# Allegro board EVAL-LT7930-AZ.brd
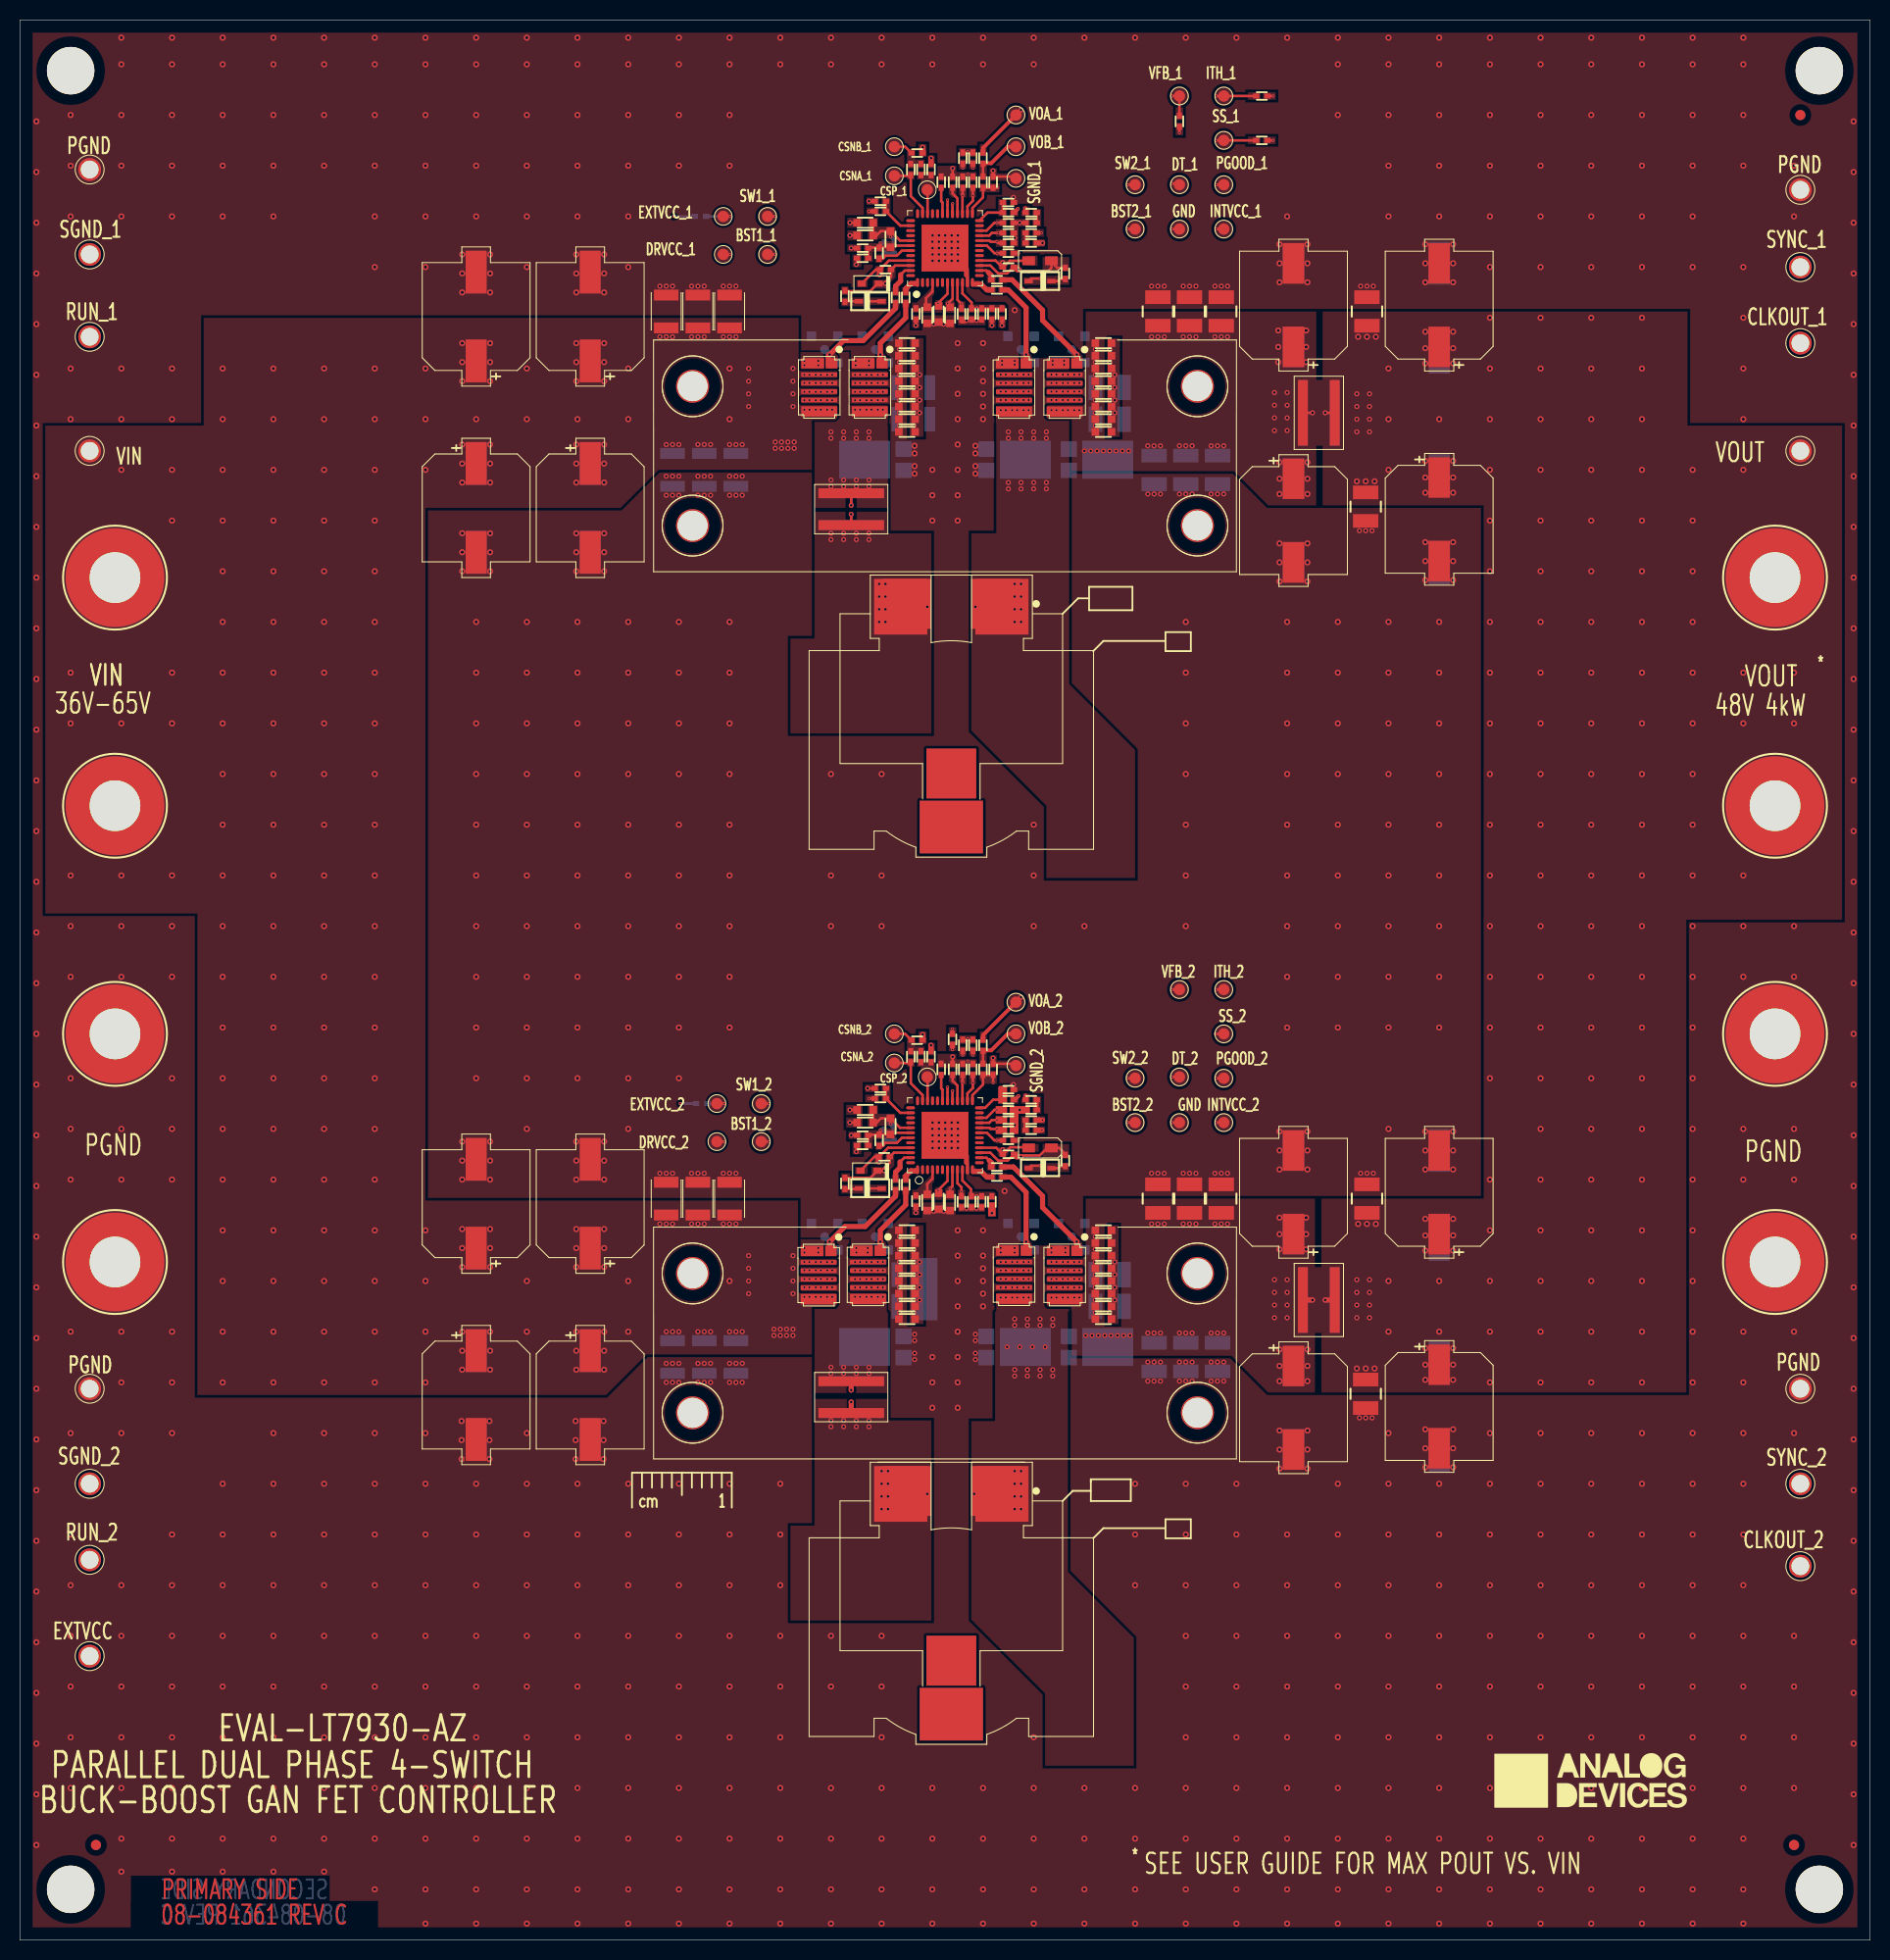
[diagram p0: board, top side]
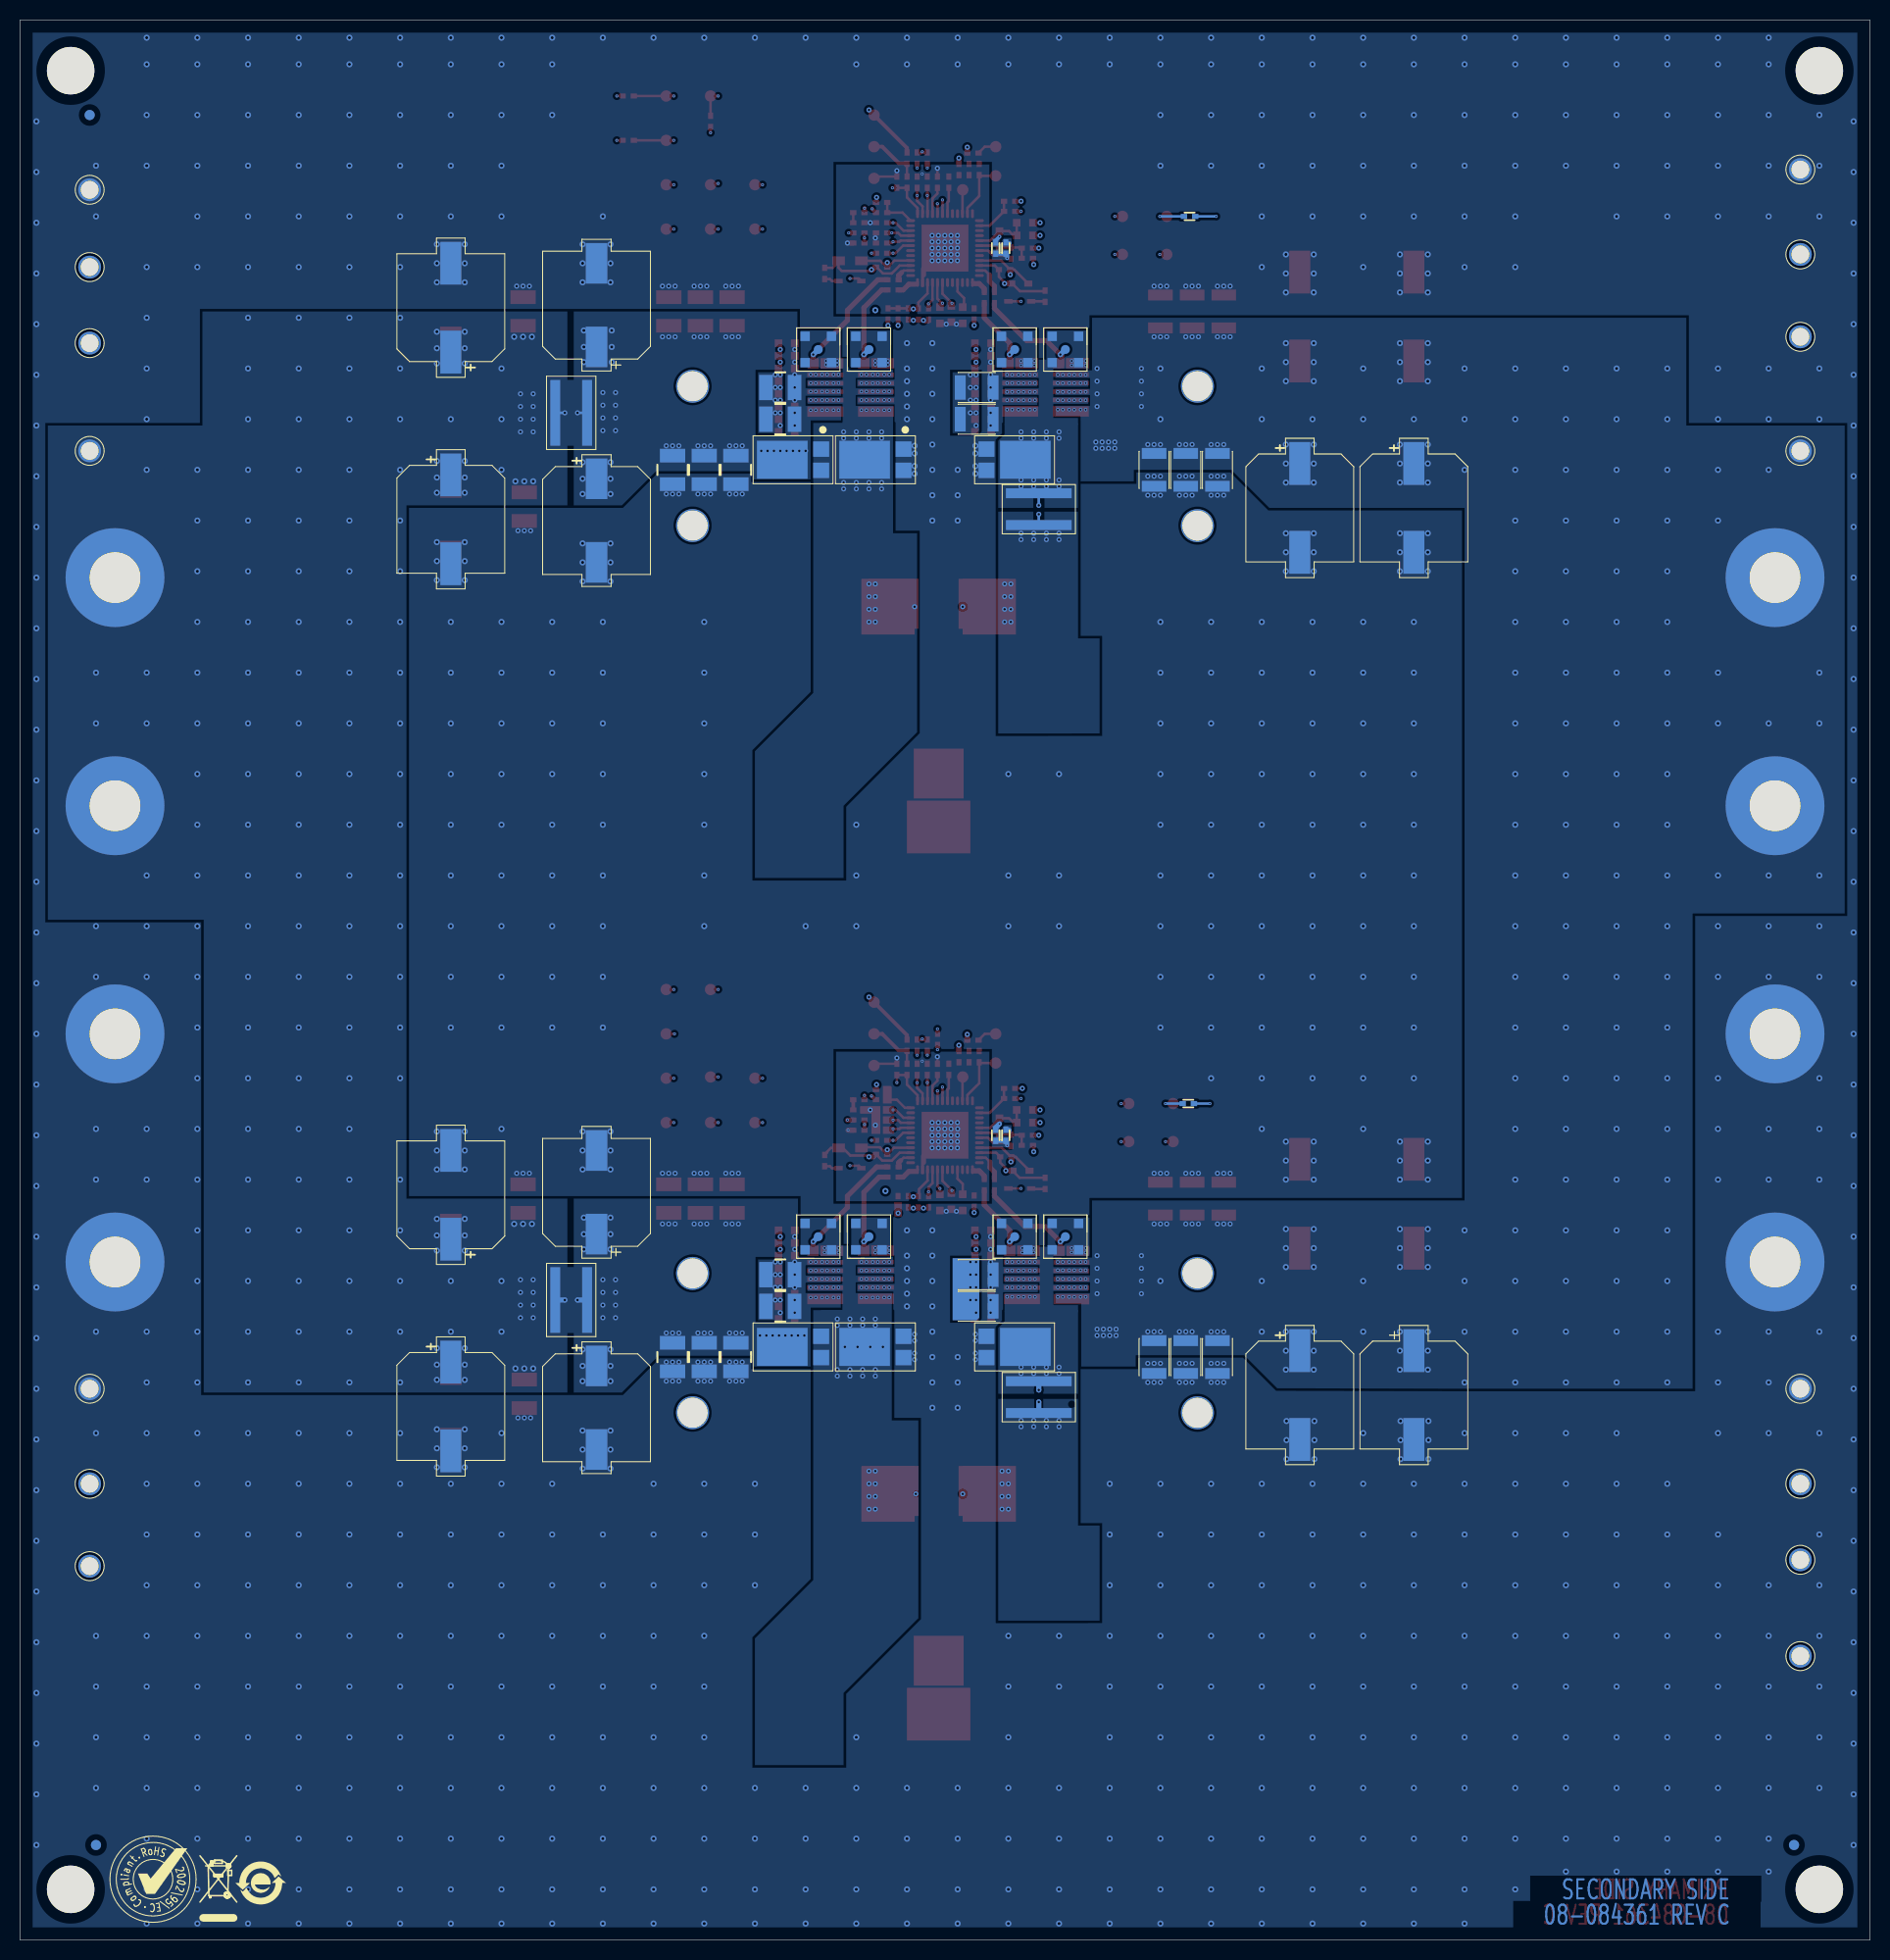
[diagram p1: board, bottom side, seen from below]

Outline 185.42 x 192.41 mm; copper layers: TOP, LAYER_2, LAYER_3, LAYER_4, LAYER_5, LAYER_6, LAYER_7, BOTTOM. Coordinates in mm from the lower left corner of the outline.
Outline path: 0,192.41 0,0 185.42,0 185.42,192.41 0,192.41

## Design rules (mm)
constraint set DEFAULT: min track width 0.254
net group _N77: nets _N77 UNNAMED_2_ADLTC7878V2_I124_BG2
net group SS_1: nets SS_1 SS_2
net group UNNAMED_1_ADLTC7878V2_I139_BG1: nets UNNAMED_1_ADLTC7878V2_I139_BG1 UNNAMED_1_RES_I73_N1
net group UNNAMED_1_ADLTC7878V2_I139_BG2: nets UNNAMED_1_ADLTC7878V2_I139_BG2 UNNAMED_1_RES_I87_N1
net group UNNAMED_1_ADLTC7878V2_I139_TG1: nets UNNAMED_1_ADLTC7878V2_I139_TG1 UNNAMED_1_RES_I72_N1
net group UNNAMED_1_ADLTC7878V2_I139_TG2: nets UNNAMED_1_ADLTC7878V2_I139_TG2 UNNAMED_1_RES_I115_N1
net group UNNAMED_2_ADLTC7878V2_I124_BG1: nets UNNAMED_2_ADLTC7878V2_I124_BG1 UNNAMED_2_RES_I64_N1
net group UNNAMED_2_ADLTC7878V2_I124_TG1: nets UNNAMED_2_ADLTC7878V2_I124_TG1 UNNAMED_2_RES_I63_N1
net group UNNAMED_2_ADLTC7878V2_I124_TG2: nets UNNAMED_2_ADLTC7878V2_I124_TG2 UNNAMED_2_RES_I106_N1
net group _N327: nets _N183 _N184 _N327 _N400 UNNAMED_1_ADLTC7878V2_I139_IS_1 UNNAMED_1_ADLTC7878V2_I139_IS_2 UNNAMED_1_ADLTC7878V2_I139_ISNS
net group _N339: nets _N144 _N145 _N339 _N399 UNNAMED_2_ADLTC7878V2_I124_IS_1 UNNAMED_2_ADLTC7878V2_I124_IS_2 UNNAMED_2_ADLTC7878V2_I124_ISNS
net group EXTVCC: nets EXTVCC EXTVCC_2 UNNAMED_1_ADLTC7878V2_I139_VOUT UNNAMED_2_ADLTC7878V2_I124_VOUT
net group ITH_1: nets ITH_1 ITH_2 UNNAMED_1_CAP_I38_N1 UNNAMED_2_CAP_I32_N1
net group UNNAMED_2_CAP_I92_N2: nets UNNAMED_2_ADLTC7878V2_I124_CSN UNNAMED_2_ADLTC7878V2_I124_CSP UNNAMED_2_CAP_I92_N2

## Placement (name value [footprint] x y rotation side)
C1  33uF  [CPLSMSQ406H413]  45.72 143.51 270 top
C2  33uF  [CPLSMSQ406H413]  57.15 143.51 270 top
C3  4.7uF  [C1210H87]  64.77 163.19 90 top
C4  4.7uF  [C1210H87]  67.94 163.19 90 top
C5  4.7uF  [C1210H87]  71.12 163.19 90 top
C6  4.7uF  [C1210H87]  71.75 147.32 270 bottom
C7  4.7uF  [C1210H87]  65.41 147.32 270 bottom
C8  4.7uF  [C1210H87]  68.58 147.32 270 bottom
C9  4.7uF  [C1210H87]  89.53 152.4 180 bottom
C10  4.7uF  [C1210H87]  89.53 155.57 180 bottom
C11  0.1UF  [C0402]  99.06 170.05 0 top
C12  1UF  [C0603]  90.93 162.81 270 top
C13  TBD0402  [C0402]  95.38 162.94 270 top
C14  100PF  [C0402]  99.06 172.09 0 top
C15  0.022uF  [C0402]  101.35 172.09 180 top
C16  0.47UF  [C0402]  86.74 167.39 180 top
C17  TBD0402  [C0402]  86.11 169.04 90 top
C18  0.01uF  [C0603]  87.25 170.43 90 top
C19  0.47UF  [C0402]  99.06 167.64 0 top
C20  1UF  [C0603]  93.22 162.81 270 top
C21  4.7uF  [C0402]  94.36 162.94 270 top
C22  TBD0402  [C0402]  90.3 177.42 90 top
C23  6.8uF  [C0603]  92.08 162.94 270 top
C24  10UF  [C1210H110]  120.4 163.19 90 top
C25  10UF  [C1210H110]  117.22 163.19 90 top
C26  10UF  [C1210H110]  114.05 163.19 90 top
C27  10UF  [C1210H110]  113.67 147.32 270 bottom
C28  10UF  [C1210H110]  120.02 147.32 270 bottom
C29  10UF  [C1210H110]  109.22 155.57 0 bottom
C30  10UF  [C1210H110]  109.22 152.4 0 bottom
C31  10UF  [C1210H110]  116.84 147.32 270 bottom
C32  47UF  [CPLSMSQ406H433]  142.24 163.83 90 top
C33  47UF  [CPLSMSQ406H433]  127.64 163.83 90 top
C34  33uF  [CPLSMSQ406H413]  45.72 54.61 270 bottom
C35  33uF  [CPLSMSQ406H413]  57.15 54.61 270 top
C36  4.7uF  [C1210H87]  64.77 74.3 90 top
C37  4.7uF  [C1210H87]  67.94 74.3 90 top
C38  4.7uF  [C1210H87]  71.12 74.3 90 top
C39  4.7uF  [C1210H87]  71.75 58.42 270 bottom
C40  4.7uF  [C1210H87]  68.58 58.42 270 bottom
C41  4.7uF  [C1210H87]  65.41 58.42 270 bottom
C42  4.7uF  [C1210H87]  89.53 66.67 180 bottom
C43  4.7uF  [C1210H87]  89.53 63.5 180 bottom
C44  0.1UF  [C0402]  99.06 81.15 0 top
C45  1UF  [C0603]  90.93 73.91 270 top
C46  TBD0402  [C0402]  95.38 73.98 270 top
C47  100PF  [C0402]  99.06 83.19 0 top
C48  0.022uF  [C0402]  101.35 83.19 180 top
C49  0.47UF  [C0402]  86.61 78.49 180 top
C50  TBD0402  [C0402]  86.11 80.14 90 top
C51  0.01uF  [C0603]  87.25 81.53 90 top
C52  0.47UF  [C0402]  99.06 78.74 0 top
C53  1UF  [C0603]  93.22 73.91 270 top
C54  4.7uF  [C0402]  94.36 73.98 270 top
C55  TBD0402  [C0402]  90.3 88.52 90 top
C56  6.8uF  [C0603]  92.08 74.04 270 top
C57  10UF  [C1210H110]  116.84 58.42 270 bottom
C58  10UF  [C1210H110]  113.67 58.42 270 bottom
C59  10UF  [C1210H110]  117.22 74.3 90 top
C60  10UF  [C1210H110]  120.02 58.42 270 bottom
C61  10UF  [C1210H110]  114.05 74.3 90 top
C62  10UF  [C1210H110]  120.4 74.3 90 top
C63  10UF  [C1210H110]  109.22 66.67 0 bottom
C64  10UF  [C1210H110]  109.22 63.5 0 bottom
C65  47UF  [CPLSMSQ406H433]  142.24 74.93 90 top
C66  47UF  [CPLSMSQ406H433]  127.64 74.93 90 top
C67  TBD0402  [C0402]  99.06 171.07 0 top
C68  TBD0402  [C0402]  99.06 82.17 0 top
C69  1UF  [C0603]  88.9 160.02 180 top
C70  1UF  [C0603]  88.9 158.75 180 top
C71  1UF  [C0603]  88.9 157.48 180 top
C72  1UF  [C0603]  88.9 156.21 180 top
C73  1UF  [C0603]  88.9 154.94 180 top
C74  1UF  [C0603]  88.9 153.67 180 top
C75  1UF  [C0603]  88.9 152.4 180 top
C76  1UF  [C0603]  88.9 151.13 180 top
C77  1UF  [C0603]  108.58 160.02 0 top
C78  1UF  [C0603]  108.58 158.75 0 top
C79  1UF  [C0603]  108.58 157.48 0 top
C80  1UF  [C0603]  108.58 156.21 0 top
C81  1UF  [C0603]  108.58 154.94 0 top
C82  1UF  [C0603]  108.58 153.67 0 top
C83  1UF  [C0603]  108.58 152.4 0 top
C84  1UF  [C0603]  108.58 151.13 0 top
C85  47UF  [CPLSMSQ406H433]  127.64 142.24 270 top
C86  47UF  [CPLSMSQ406H433]  127.64 142.24 270 bottom
C87  1UF  [C0603]  88.9 71.12 180 top
C88  1UF  [C0603]  88.9 69.85 180 top
C89  1UF  [C0603]  88.9 68.58 180 top
C90  1UF  [C0603]  88.9 67.31 180 top
C91  1UF  [C0603]  88.9 66.04 180 top
C92  1UF  [C0603]  88.9 64.77 180 top
C93  1UF  [C0603]  88.9 63.5 180 top
C94  1UF  [C0603]  88.9 62.23 180 top
C95  1UF  [C0603]  108.58 71.12 0 top
C96  1UF  [C0603]  108.58 69.85 0 top
C97  1UF  [C0603]  108.58 68.58 0 top
C98  1UF  [C0603]  108.58 67.31 0 top
C99  1UF  [C0603]  108.58 66.04 0 top
C100  1UF  [C0603]  108.58 64.77 0 top
C101  1UF  [C0603]  108.58 63.5 0 top
C102  1UF  [C0603]  108.58 62.23 0 top
C103  47UF  [CPLSMSQ406H433]  127.64 53.34 270 bottom
C104  47UF  [CPLSMSQ406H433]  127.64 53.34 270 top
C176  33uF  [CPLSMSQ406H413]  45.72 143.51 270 bottom
C177  33uF  [CPLSMSQ406H413]  57.15 143.51 270 bottom
C178  47UF  [CPLSMSQ406H433]  142.24 142.37 270 top
C179  47UF  [CPLSMSQ406H433]  127.64 163.83 90 bottom
C180  33uF  [CPLSMSQ406H413]  45.72 54.61 270 top
C181  33uF  [CPLSMSQ406H413]  57.15 54.61 270 bottom
C182  47UF  [CPLSMSQ406H433]  142.24 53.47 270 top
C183  47UF  [CPLSMSQ406H433]  127.64 74.93 90 bottom
C196  10UF  [C1210H110]  134.87 143.64 270 top
C197  10UF  [C1210H110]  135 163.19 90 top
C198  10UF  [C1210H110]  135 74.3 90 top
C199  10UF  [C1210H110]  134.87 54.74 270 top
C206  33uF  [CPLSMSQ406H413]  45.72 162.69 90 top
C207  33uF  [CPLSMSQ406H413]  57.15 162.69 90 top
C208  33uF  [CPLSMSQ406H413]  142.24 163.58 90 bottom
C209  33uF  [CPLSMSQ406H413]  142.24 142.37 270 bottom
C210  33uF  [CPLSMSQ406H413]  45.72 73.79 90 top
C211  33uF  [CPLSMSQ406H413]  57.15 73.79 90 top
C212  33uF  [CPLSMSQ406H413]  142.24 74.68 90 bottom
C213  33uF  [CPLSMSQ406H413]  142.24 53.47 270 bottom
D1  BAT46WJ,115  [SOD323F]  85.22 164.21 0 top
D2  BAT46WJ,115  [SOD323F]  102.23 166.24 180 top
D3  BAT46WJ,115  [SOD323F]  85.22 75.31 0 top
D4  BAT46WJ,115  [SOD323F]  102.23 77.34 180 top
D5  CMOZ5L1 TR PBFREE  [SOD523_B]  85.22 165.99 180 top
D7  PMEG100T030ELPEZ  [SOT1289B]  85.72 148.34 180 bottom
D8  CMDZ5231B TR PBFREE  [SOD323]  102.23 168.28 180 top
D10  PMEG100T030ELPEZ  [SOT1289B]  85.72 59.44 180 bottom
D11  CMDZ5231B TR PBFREE  [SOD323]  102.23 79.38 180 top
D12  CMOZ5L1 TR PBFREE  [SOD523_B]  85.09 77.09 180 top
D13  PMEG100T030ELPEZ  [SOT1289B]  99.69 148.34 0 bottom
D14  PMEG100T030ELPEZ  [SOT1289B]  107.95 148.34 0 bottom
D15  PMEG100T030ELPEZ  [SOT1289B]  99.69 59.44 0 bottom
D16  PMEG100T030ELPEZ  [SOT1289B]  107.95 59.44 0 bottom
J1  CKFH1032-10  [CNCFCKFH1032-10]  9.53 113.67 0 top
J2  CKFH1032-10  [CNCFCKFH1032-10]  9.53 90.81 0 top
J3  CKFH1032-10  [CNCFCKFH1032-10]  175.9 113.67 0 top
J4  CKFH1032-10  [CNCFCKFH1032-10]  175.9 90.81 0 top
J5  CKFH1032-10  [CNCFCKFH1032-10]  9.53 136.53 0 top
J6  CKFH1032-10  [CNCFCKFH1032-10]  9.53 67.94 0 top
J7  CKFH1032-10  [CNCFCKFH1032-10]  175.9 136.53 0 top
J8  CKFH1032-10  [CNCFCKFH1032-10]  175.9 67.94 0 top
J12  0734152063  [CNSMASQ136H203]  105.41 159.38 180 bottom
J13  0734152063  [CNSMASQ136H203]  80.64 70.48 180 bottom
J14  0734152063  [CNSMASQ136H203]  85.72 70.48 180 bottom
J15  0734152063  [CNSMASQ136H203]  100.33 70.48 180 bottom
J16  0734152063  [CNSMASQ136H203]  105.41 70.48 180 bottom
J17  0734152063  [CNSMASQ136H203]  100.33 159.38 180 bottom
J18  0734152063  [CNSMASQ136H203]  80.64 159.38 180 bottom
J19  0734152063  [CNSMASQ136H203]  85.72 159.38 180 bottom
L1  6.8UH  [LSML1102W764H728]  93.34 122.05 180 top
L1_1  2.2UH  [LSML858W571H571]  93.34 125.4 180 top
L2  6.8UH  [LSML1102W764H728]  93.34 33.15 180 top
L2_1  2.2UH  [LSML858W571H571]  93.34 36.5 180 top
NOREF  -  []  265.1 155.59 0 top
NOREF#2  -  [unnamed#2]  7.62 9.53 0 top
NOREF#3  -  [unnamed#2]  5.08 187.32 180 top
NOREF#4  -  []  -55.88 -186.06 0 top
NOREF#5  -  []  97.16 201.93 0 top
NOREF#6  -  []  0 192.41 0 top
NOREF#7  -  []  25.4 5.71 270 top
NOREF#8  -  []  185.42 0 90 top
NOREF#9  VAL  []  92.71 59.82 0 top
NOREF#10  -  []  -55.88 -186.06 0 top
NOREF#11  -  []  0 0 0 top
NOREF#12  -  []  185.42 0 90 top
NOREF#13  -  [unnamed#2]  177.8 9.53 0 top
NOREF#14  -  [unnamed#2]  178.44 182.88 0 top
NOREF#15  -  [unnamed#2]  180.34 187.32 180 top
NOREF#16  -  []  301.29 97.81 0 top
NOREF#17  -  []  0 192.41 270 top
NOREF#18  -  []  33.27 -151.76 0 top
NOREF#19  -  []  -201.93 -255.91 0 top
NOREF#20  VAL  []  92.71 148.72 0 top
NOREF#21  -  []  157.35 14.61 0 top
NOREF#22  -  [unnamed#2]  5.08 5.08 180 top
NOREF#23  -  []  326.06 48.28 0 top
NOREF#24  -  []  185.42 192.41 180 top
NOREF#25  -  []  -201.93 -255.91 0 top
NOREF#26  -  [unnamed#2]  180.34 5.08 180 top
NOREF#27  -  []  269.37 142.24 0 top
NOREF#28  -  []  256.97 -50.4 0 top
NOREF#29  -  []  61.34 43.33 0 top
NOREF#30  -  []  -55.88 -186.06 0 top
NOREF#31  -  []  165.74 1.91 180 bottom
NOREF#32  -  []  161.29 5.71 180 bottom
NOREF#33  -  [unnamed#2]  7.62 9.53 180 bottom
NOREF#34  -  [unnamed#2]  177.8 9.53 180 bottom
NOREF#35  -  []  172.09 6.1 180 bottom
NOREF#36  -  [unnamed#2]  178.44 182.88 180 bottom
P1  9774010243R  [CNWURTH9774010243R]  67.41 155.7 0 top
P2  9774010243R  [CNWURTH9774010243R]  67.41 141.73 0 top
P3  9774010243R  [CNWURTH9774010243R]  118.01 155.7 0 top
P4  9774010243R  [CNWURTH9774010243R]  118.01 141.74 0 top
P5  9774010243R  [CNWURTH9774010243R]  67.41 66.8 0 top
P6  9774010243R  [CNWURTH9774010243R]  67.41 52.83 0 top
P7  9774010243R  [CNWURTH9774010243R]  118.01 66.8 0 top
P8  9774010243R  [CNWURTH9774010243R]  118.01 52.84 0 top
Q1  EPC2361  [DIE7_5X3]  80.11 155.59 270 top
Q2  EPC2361  [DIE7_5X3]  85.18 155.59 270 top
Q3  EPC2361  [DIE7_5X3]  99.62 155.57 270 top
Q4  EPC2361  [DIE7_5X3]  104.7 155.57 270 top
Q5  EPC2361  [DIE7_5X3]  80.05 66.63 270 top
Q6  EPC2361  [DIE7_5X3]  85 66.66 270 top
Q7  EPC2361  [DIE7_5X3]  99.63 66.67 270 top
Q8  EPC2361  [DIE7_5X3]  104.71 66.65 270 top
R1  0  [R0402]  93.46 90.25 270 top
R2  0  [R0402]  98.42 162.94 270 top
R3  0  [R0402]  124.46 180.34 0 top
R4  0  [R0402]  124.46 184.78 0 top
R5  0  [R0402]  116.2 182.25 270 top
R6  1  [R0402]  89.79 74.04 90 top
R7  301K  [R0402]  97.41 162.94 90 top
R8  10.7K  [R0402]  96.39 162.94 90 top
R9  0  [R0402]  87.76 164.59 90 top
R10  0  [R0402]  88.77 164.59 90 top
R11  TBD0402  [R0402]  101.35 171.07 180 top
R12  9.09K  [R0402]  101.35 173.1 0 top
R13  0  [R0402]  84.45 168.53 0 top
R14  0.002  [R1225H28]  83.31 143.38 270 top
R15  0.002  [R1225H28]  83.31 143.38 270 bottom
R16  1  [R0603]  84.71 170.81 0 top
R17  0  [R0402]  86.61 169.54 90 bottom
R18  54.9K  [R0402]  93.47 176.15 90 top
R19  TBD0402  [R0402]  84.45 169.54 0 top
R20  TBD0402  [R0402]  92.33 176.15 90 top
R21  TBD0402  [R0402]  87.63 169.54 90 bottom
R22  0  [R0402]  95.5 176.15 90 top
R23  TBD0603  [R0603]  84.71 172.09 0 top
R24  0  [R0402]  94.49 176.15 90 top
R25  TBD0402  [R0402]  94.49 178.56 90 top
R26  TBD0402  [R0402]  95.5 178.56 90 top
R27  100K  [R0402]  99.06 169.04 0 top
R28  0  [R0402]  97.92 165.35 180 top
R29  0  [R0402]  89.28 177.42 90 top
R30  0  [R0402]  97.92 166.37 180 top
R31  0  [R0402]  91.31 177.42 90 top
R32  0  [R0402]  89.92 179.07 0 top
R33  0  [R1225H28]  130.18 153.03 0 top
R34  0  [R0402]  96.52 178.56 270 top
R35  475K  [R0402]  96.52 176.15 270 top
R36  10K  [R0402]  97.54 176.15 90 top
R37  301K  [R0402]  97.41 73.98 90 top
R38  10.7K  [R0402]  96.39 73.98 90 top
R39  0  [R0402]  87.76 75.69 90 top
R40  0  [R0402]  88.77 75.69 90 top
R41  TBD0402  [R0402]  101.35 82.17 180 top
R42  9.09K  [R0402]  101.35 84.2 0 top
R43  0  [R0402]  84.45 79.63 0 top
R44  0.002  [R1225H28]  83.31 54.41 270 top
R45  0.002  [R1225H28]  83.31 54.41 270 bottom
R46  1  [R0603]  84.71 81.92 0 top
R47  0  [R0402]  86.61 80.64 90 bottom
R48  54.9K  [R0402]  93.47 87.25 90 top
R49  TBD0402  [R0402]  84.45 80.64 0 top
R50  TBD0402  [R0402]  92.33 87.25 90 top
R51  TBD0402  [R0402]  87.63 80.64 90 bottom
R52  0  [R0402]  95.5 87.25 90 top
R53  TBD0603  [R0603]  84.71 83.19 0 top
R54  0  [R0402]  94.49 87.25 90 top
R55  TBD0402  [R0402]  94.49 89.66 90 top
R56  TBD0402  [R0402]  95.5 89.66 90 top
R57  100K  [R0402]  99.06 80.14 0 top
R58  0  [R0402]  97.92 76.45 180 top
R59  0  [R0402]  89.28 88.52 90 top
R60  0  [R0402]  97.92 77.47 180 top
R61  0  [R0402]  91.31 88.52 90 top
R62  0  [R0402]  89.92 90.17 0 top
R63  0  [R1225H28]  130.18 64.14 0 top
R64  0  [R0402]  96.52 89.66 270 top
R65  475K  [R0402]  96.52 87.25 270 top
R66  10K  [R0402]  97.54 87.25 90 top
R67  1  [R0402]  86.23 84.33 0 top
R68  5.1  [R0402]  86.23 85.34 180 top
R69  1  [R0402]  89.79 162.94 90 top
R70  1  [R0402]  86.23 173.23 0 top
R71  5.1  [R0402]  86.23 174.24 180 top
R72  21K  [R0402]  99.06 174.12 0 top
R73  27.4K  [R0402]  101.35 170.05 0 top
R74  953K  [R0402]  99.06 173.1 180 top
R75  21K  [R0402]  99.06 85.22 0 top
R76  27.4K  [R0402]  101.35 81.15 0 top
R77  953K  [R0402]  99.06 84.2 180 top
R78  1  [R0402]  82.68 164.72 90 top
R79  1  [R0402]  104.78 167 90 top
R80  1  [R0402]  82.68 75.82 90 top
R81  1  [R0402]  104.78 78.11 90 top
R82  0  [R0402]  68.2 172.72 180 bottom
R83  0  [R0402]  68.33 83.82 180 bottom
R190  0  [R1225H28]  130.18 153.03 0 bottom
R191  0  [R1225H28]  130.18 64.14 0 bottom
TP1  2308-2-00-80-00-00-07-0  [CNMILLMAX2308]  6.99 149.22 0 top
TP2  TESTPAD  [TPSMC40]  116.2 175.9 0 top
TP3  TESTPAD  [TPSMC40]  116.2 171.45 0 top
TP4  2308-2-00-80-00-00-07-0  [CNMILLMAX2308]  6.99 55.24 0 top
TP5  2308-2-00-80-00-00-07-0  [CNMILLMAX2308]  6.99 160.66 0 top
TP6  2308-2-00-80-00-00-07-0  [CNMILLMAX2308]  6.99 168.91 0 top
TP7  2308-2-00-80-00-00-07-0  [CNMILLMAX2308]  178.44 167.64 0 top
TP8  2308-2-00-80-00-00-07-0  [CNMILLMAX2308]  178.44 160.02 0 top
TP9  TESTPAD  [TPSMC40]  120.65 180.34 0 top
TP10  TESTPAD  [TPSMC40]  120.65 184.78 0 top
TP11  TESTPAD  [TPSMC40]  87.63 176.78 90 top
TP12  TESTPAD  [TPSMC40]  70.48 172.72 0 top
TP13  TESTPAD  [TPSMC40]  87.63 179.71 90 top
TP14  TESTPAD  [TPSMC40]  120.65 171.45 0 top
TP15  TESTPAD  [TPSMC40]  120.65 175.9 0 top
TP16  TESTPAD  [TPSMC40]  90.93 175.39 90 top
TP17  TESTPAD  [TPSMC40]  70.48 168.91 0 top
TP18  TESTPAD  [TPSMC40]  116.2 184.78 0 top
TP19  TESTPAD  [TPSMC40]  99.82 182.88 90 top
TP20  TESTPAD  [TPSMC40]  99.82 179.71 90 top
TP21  TESTPAD  [TPSMC40]  99.82 176.53 90 top
TP22  2308-2-00-80-00-00-07-0  [CNMILLMAX2308]  178.44 149.22 0 top
TP23  TESTPAD  [TPSMC40]  116.2 86.49 0 top
TP24  TESTPAD  [TPSMC40]  116.2 81.92 0 top
TP25  2308-2-00-80-00-00-07-0  [CNMILLMAX2308]  178.44 55.24 0 top
TP26  TESTPAD  [TPSMC40]  120.65 90.81 0 top
TP27  TESTPAD  [TPSMC40]  120.65 95.25 0 top
TP28  TESTPAD  [TPSMC40]  74.93 168.91 0 top
TP29  TESTPAD  [TPSMC40]  74.93 172.72 0 top
TP30  2308-2-00-80-00-00-07-0  [CNMILLMAX2308]  6.99 38.1 0 top
TP31  2308-2-00-80-00-00-07-0  [CNMILLMAX2308]  6.99 45.72 0 top
TP32  2308-2-00-80-00-00-07-0  [CNMILLMAX2308]  178.44 45.72 0 top
TP33  2308-2-00-80-00-00-07-0  [CNMILLMAX2308]  178.44 37.47 0 top
TP34  2308-2-00-80-00-00-07-0  [CNMILLMAX2308]  6.99 177.42 0 top
TP35  2308-2-00-80-00-00-07-0  [CNMILLMAX2308]  178.44 175.39 0 top
TP36  2308-2-00-80-00-00-07-0  [CNMILLMAX2308]  6.99 28.45 90 top
TP37  TESTPAD  [TPSMC40]  69.85 83.82 0 top
TP38  TESTPAD  [TPSMC40]  87.63 90.81 90 top
TP39  TESTPAD  [TPSMC40]  120.65 81.92 0 top
TP40  TESTPAD  [TPSMC40]  120.65 86.36 0 top
TP41  TESTPAD  [TPSMC40]  90.93 86.49 90 top
TP42  TESTPAD  [TPSMC40]  69.85 80.01 0 top
TP43  TESTPAD  [TPSMC40]  116.2 95.25 0 top
TP44  TESTPAD  [TPSMC40]  99.82 93.98 90 top
TP45  TESTPAD  [TPSMC40]  99.82 90.81 90 top
TP46  TESTPAD  [TPSMC40]  99.82 87.63 90 top
TP47  TESTPAD  [TPSMC40]  111.76 175.9 0 top
TP48  TESTPAD  [TPSMC40]  111.76 171.45 0 top
TP49  TESTPAD  [TPSMC40]  74.3 80.01 0 top
TP50  TESTPAD  [TPSMC40]  74.3 83.82 0 top
TP51  TESTPAD  [TPSMC40]  111.76 86.36 0 top
TP52  TESTPAD  [TPSMC40]  111.76 81.92 0 top
TP53  TESTPAD  [TPSMC40]  87.63 87.88 0 top
U1  LT7930AUK#PBF  [QFN48_7X7_PAD4_7X4_7_A]  92.71 169.54 0 top
U2  LT7930AUK#PBF  [QFN48_7X7_PAD4_7X4_7_A]  92.71 80.64 0 top

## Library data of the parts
C1 C2 C34 C35 C176 C177 C180 C181 C206-C213 = CAPP: User Part Number: UPN; Tolerance: 20; alternate symbols: (CPLSMSQ406H413); tolerance: 20
C3-C10 C36-C43 = CAP: Tolerance: 10; User Part Number: UPN; alternate symbols: (C1210H87); tolerance: 10
C11 C15 C16 C19 C21 C44 C48 C49 C52 C54 = CAP: Tolerance: 10; User Part Number: UPN; alternate symbols: (C0402); tolerance: 10
C12 C18 C20 C23 C45 C51 C53 C56 C69-C84 C87-C102 = CAP: Tolerance: 10; User Part Number: UPN; alternate symbols: (C0603); tolerance: 10
C13 C17 C22 C46 C50 C55 C67 C68 = CAP: User Part Number: UPN; alternate symbols: (C0402)
C14 C47 = CAP: Tolerance: 20; User Part Number: UPN; alternate symbols: (C0402); tolerance: 20
C24-C31 C57-C64 C196-C199 = CAP: User Part Number: UPN; Tolerance: 10; alternate symbols: (C1210H110); tolerance: 10
C32 C33 C65 C66 C85 C86 C103 C104 C178 C179 C182 C183 = CAPP: User Part Number: UPN; Tolerance: 20; alternate symbols: (CPLSMSQ406H433); tolerance: 20
D1-D4 = DIOSCHOTTKY: Tolerance: N/A; User Part Number: UPN; alternate symbols: (SOD323F); tolerance: N/A
D5 D12 = DIOZNR: Tolerance: 5; User Part Number: UPN; alternate symbols: (SOD523_B); tolerance: 5
D7 D10 D13-D16 = DIOSCHOTTKY_3P: User Part Number: UPN; Tolerance: N/A; alternate symbols: (SOT1289B); tolerance: N/A
D8 D11 = DIOZNR: Tolerance: 5; User Part Number: UPN; alternate symbols: (SOD323); tolerance: 5
J1-J8 = CNTP1P: Tolerance: N/A; User Part Number: UPN; alternate symbols: (CNCFCKFH1032-10_C380D200); tolerance: N/A
J12-J19 = CNBNC5P: Tolerance: N/A; User Part Number: UPN; alternate symbols: (CNSMASQ136H203); tolerance: N/A
L1 L2 = IND: User Part Number: UPN; Tolerance: 15; alternate symbols: (LSML1102W764H728); tolerance: 15
L1_1 L2_1 = IND: Tolerance: 15; User Part Number: UPN; alternate symbols: (LSML858W571H571); tolerance: 15
NOREF#9 = -: Tolerance: TOL; User Part Number: UPN
NOREF#20 = -: User Part Number: UPN; Tolerance: TOL
P1-P8 = CN1P: Tolerance: N/A; User Part Number: UPN; alternate symbols: (CNWURTH9774010243R); tolerance: N/A
Q1-Q8 = TRANNGANFET7P_V3: User Part Number: UPN; Tolerance: N/A; alternate symbols: (DIE7_5X3); tolerance: N/A
R1-R5 R9 R10 R13 R17 R22 R24 R28-R32 R34 R39 R40 R43 R47 R52 R54 R58-R62 R64 R82 R83 = RES: Tolerance: JUMPER; User Part Number: UPN; alternate symbols: (R0402); tolerance: JUMPER
R6 R67-R71 = RES: Tolerance: 5; User Part Number: UPN; alternate symbols: (R0402); tolerance: 5
R7 R8 R12 R18 R27 R35-R38 R42 R48 R57 R65 R66 R72-R77 = RES: Tolerance: 1; User Part Number: UPN; alternate symbols: (R0402); tolerance: 1
R11 R19-R21 R25 R26 R41 R49-R51 R55 R56 R78-R81 = RES: User Part Number: UPN; alternate symbols: (R0402)
R14 R15 R44 R45 = RES: User Part Number: UPN; Tolerance: 2; alternate symbols: (R1225H28); tolerance: 2
R16 R23 R46 R53 = RES: User Part Number: UPN; alternate symbols: (R0603)
R33 R63 R190 R191 = RES: User Part Number: UPN; Tolerance: N/A; alternate symbols: (R1225H28); tolerance: N/A
TP1 TP4-TP8 TP22 TP25 TP30-TP36 = CNTP1P: User Part Number: UPN; Tolerance: N/A; alternate symbols: (CNMILLMAX2308); tolerance: N/A
TP2 TP3 TP9-TP21 TP23 TP24 TP26-TP29 TP37-TP53 = NCTESTPAD: Tolerance: N/A; User Part Number: UPN; alternate symbols: (TPSMC40); tolerance: N/A
U1 U2 = ADLT7930: Tolerance: N/A; User Part Number: UPN; alternate symbols: (QFN48_7X7_PAD4_7X4_7_A); tolerance: N/A

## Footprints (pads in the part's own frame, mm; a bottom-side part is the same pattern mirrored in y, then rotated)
C0402
  rect 0.635x0.508 smd: 1(-0.564,0) 2(0.564,0)
C0603
  rect 0.762x0.762 smd: 1(-0.813,0) 2(0.813,0)
C1210H87
  rect 1.092x2.464 smd: 1(-1.646,0) 2(1.646,0)
C1210H110
  rect 1.372x2.54 smd: 1(-1.431,0) 2(1.431,0)
CNCFCKFH1032-10
  round 9.906 hole 5.08: 1(0,0)
CNMILLMAX2308
  round 2.286 hole 1.778: 1(0,0)
CNSMASQ136H203
  round 0.889 smd: 1(0,0)
  rect 0.94x0.94 smd: 2(-1.32,-1.32) 3(1.32,-1.32) 4(1.32,1.32) 5(-1.32,1.32)
CNWURTH9774010243R
  round 3.302 hole 2.997 unplated: (0,0)
  round 0 smd: 1(0,0)
CPLSMSQ406H413
  rect 4.293x2.108 smd: N(4.45,0) P(-4.45,0)
CPLSMSQ406H433
  rect 4.064x2.159 smd: N(4.187,0) P(-4.187,0)
DIE7_5X3
  rect 1.041x1.143 smd: 1(-2.414,1.222)
  rect 1.041x2.286 smd: 2(-2.414,-0.658)
  rect 0.457x3.607 smd: 3(-1.275,0) 4(-0.425,0) 5(0.425,0) 6(1.275,0)
  rect 1.041x3.607 smd: 7(2.414,0)
LSML858W571H571
  rect 5.004x5.004 smd: (0,8.502) 1(-4.502,-8.502) 2(4.502,-8.502)
LSML1102W764H728
  rect 6.35x5.283 smd: (0,10.514)
  rect 5.334x5.588 smd: 1(-5.075,-11.56) 2(5.075,-11.56)
QFN48_7X7_PAD4_7X4_7_A
  oval 0.305x0.889 smd: 1(-2.75,-3.45) 2(-2.25,-3.45) 3(-1.75,-3.45) 4(-1.25,-3.45) 5(-0.75,-3.45) 6(-0.25,-3.45) 7(0.25,-3.45) 8(0.75,-3.45) 9(1.25,-3.45) 10(1.75,-3.45) 11(2.25,-3.45) 12(2.75,-3.45) 25(2.75,3.45) 26(2.25,3.45) 27(1.75,3.45) 28(1.25,3.45) 29(0.75,3.45) 30(0.25,3.45) 31(-0.25,3.45) 32(-0.75,3.45) 33(-1.25,3.45) 34(-1.75,3.45) 35(-2.25,3.45) 36(-2.75,3.45)
  oval 0.889x0.305 smd: 13(3.45,-2.75) 14(3.45,-2.25) 15(3.45,-1.75) 16(3.45,-1.25) 17(3.45,-0.75) 18(3.45,-0.25) 19(3.45,0.25) 20(3.45,0.75) 21(3.45,1.25) 22(3.45,1.75) 23(3.45,2.25) 24(3.45,2.75) 37(-3.45,2.75) 38(-3.45,2.25) 39(-3.45,1.75) 40(-3.45,1.25) 41(-3.45,0.75) 42(-3.45,0.25) 43(-3.45,-0.25) 44(-3.45,-0.75) 45(-3.45,-1.25) 46(-3.45,-1.75) 47(-3.45,-2.25) 48(-3.45,-2.75)
  rect 4.699x4.699 smd: 49(0,0)
R0402
  rect 0.635x0.508 smd: 1(-0.564,0) 2(0.564,0)
R0603
  rect 0.762x0.762 smd: 1(-0.813,0) 2(0.813,0)
R1225H28
  rect 0.991x6.579 smd: 1(-1.595,0) 2(1.595,0)
SOD323
  rect 1.27x0.889 smd: A(1.143,0) C(-1.143,0)
SOD323F
  rect 0.838x0.457 smd: A(1.14,0) C(-1.14,0)
SOD523_B
  rect 0.813x0.61 smd: A(0.85,0) C(-0.85,0)
SOT1289B
  rect 1.6x1.549 smd: 1(-2.83,-1.065) 2(-2.83,1.065)
  rect 5.08x3.81 smd: 3(1.07,0)
TPSMC40
  round 1.143 smd: 1(0,0)
unnamed#2
  round 1.016 smd: (0,0)

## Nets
SGND: C11.2(N2) C13.2(N2) C14.2(N2) C15.2(N2) C21.2(N2) C44.2(N2) C46.2(N2) C47.2(N2) C48.2(N2) C54.2(N2) C67.2(N2) C68.2(N2) R8.1 R18.2(N2) R20.2(N2) R22.2(N2) R24.2(N2) R36.2(N2) R38.1 R48.2(N2) R50.2(N2) R52.2(N2) R54.2(N2) R66.2(N2) R73.2(N2) R76.2(N2) TP3.1(N1) TP6.1(N1) TP21.1(N1) TP24.1(N1) TP31.1(N1) TP46.1(N1) U1.49 U2.49
VIN: C1.P C2.P C3.1 C4.1 C5.1 C6.1 C7.1 C8.1 C9.1 C10.1 C34.P C35.P C36.1 C37.1 C38.1 C39.1 C40.1 C41.1 C42.1 C43.1 C69.1 C70.1 C71.1 C72.1 C73.1 C74.1 C75.1 C76.1 C87.1 C88.1 C89.1 C90.1 C91.1 C92.1 C93.1 C94.1 C176.P C177.P C180.P C181.P C206.P C207.P C210.P C211.P J1.1(N1) J5.1(N1) Q1.3 Q1.5 Q1.7 Q5.3 Q5.5 Q5.7 R6.1 R7.1 R37.1 R69.1 R74.1 R77.1 TP1.1(N1)
_N4: C67.1 R11.2(N2) R73.1 U1.21
_N10: R11.1 TP2.1(N1)
_N12: R72.1 R74.2(N2) U1.24
_N77: J15.1 Q7.1 R58.1
_N135: R41.1 TP23.1(N1)
_N140: R75.1 R77.2(N2) U2.24
_N144: D3.C R80.1
_N145: D4.C R81.1
_N183: D2.C R79.1
_N184: D1.C R78.1
_N327: L1.2(N2) L1_1.2(N2) R14.2(N2) R15.2(N2) R16.1 R19.1
_N339: L2.2(N2) L2_1.2(N2) R44.2(N2) R45.2(N2) R46.1 R49.1
_N377: C52.1 D11.A(P) D15.3(C) D16.1 D16.2 J16.2 J16.3 J16.4 J16.5(SH4) L2.1 L2_1.1 Q7.3 Q7.5 Q7.7 Q8.2 Q8.4 Q8.6(S3) R53.1 TP51.1(N1) U2.16
_N381: C19.1 D8.A(P) D13.3(C) D14.1 D14.2 J12.2 J12.3 J12.4 J12.5(SH4) L1.1 L1_1.1 Q3.3 Q3.5 Q3.7 Q4.2 Q4.4 Q4.6(S3) R23.1 TP47.1(N1) U1.16
_N399: C49.2(N2) D10.3(C) D12.A(P) J13.2 J13.3 J13.4 J13.5(SH4) Q5.2 Q5.4 Q5.6(S3) Q6.3 Q6.5 Q6.7 R43.1 R44.1 R45.1 TP50.1(N1) U2.45
_N400: C16.2(N2) D5.A(P) D7.3(C) J18.2 J18.3 J18.4 J18.5(SH4) Q1.2 Q1.4 Q1.6(S3) Q2.3 Q2.5 Q2.7 R13.1 R14.1 R15.1 TP29.1(N1) U1.45
CLKOUT_1: R1.1 TP8.1(N1) U1.29
CLKOUT_2: TP33.1(N1) U2.29
DRVCC_1: C23.1 D1.A(P) D2.A(P) TP17.1(N1) U1.7
DRVCC_2: C56.1 D3.A(P) D4.A(P) TP42.1(N1) U2.7
EXTVCC: R82.2(N2) R83.2(N2) TP36.1(N1)
EXTVCC_1: C20.1 R70.1 R82.1 TP12.1(N1) U1.8
EXTVCC_2: C53.1 R67.1 R83.1 TP37.1(N1) U2.8
GROUND: C1.N(N2) C2.N(N2) C3.2(N2) C4.2(N2) C5.2(N2) C6.2(N2) C7.2(N2) C8.2(N2) C9.2(N2) C10.2(N2) C12.2(N2) C20.2(N2) C23.2(N2) C24.2(N2) C25.2(N2) C26.2(N2) C27.2(N2) C28.2(N2) C29.2(N2) C30.2(N2) C31.2(N2) C32.N(N2) C33.N(N2) C34.N(N2) C35.N(N2) C36.2(N2) C37.2(N2) C38.2(N2) C39.2(N2) C40.2(N2) C41.2(N2) C42.2(N2) C43.2(N2) C45.2(N2) C53.2(N2) C56.2(N2) C57.2(N2) C58.2(N2) C59.2(N2) C60.2(N2) C61.2(N2) C62.2(N2) C63.2(N2) C64.2(N2) C65.N(N2) C66.N(N2) C69.2(N2) C70.2(N2) C71.2(N2) C72.2(N2) C73.2(N2) C74.2(N2) C75.2(N2) C76.2(N2) C77.2(N2) C78.2(N2) C79.2(N2) C80.2(N2) C81.2(N2) C82.2(N2) C83.2(N2) C84.2(N2) C85.N(N2) C86.N(N2) C87.2(N2) C88.2(N2) C89.2(N2) C90.2(N2) C91.2(N2) C92.2(N2) C93.2(N2) C94.2(N2) C95.2(N2) C96.2(N2) C97.2(N2) C98.2(N2) C99.2(N2) C100.2(N2) C101.2(N2) C102.2(N2) C103.N(N2) C104.N(N2) C176.N(N2) C177.N(N2) C178.N(N2) C179.N(N2) C180.N(N2) C181.N(N2) C182.N(N2) C183.N(N2) C196.2(N2) C197.2(N2) C198.2(N2) C199.2(N2) C206.N(N2) C207.N(N2) C208.N(N2) C209.N(N2) C210.N(N2) C211.N(N2) C212.N(N2) C213.N(N2) D7.1 D7.2 D10.1 D10.2 D13.1 D13.2 D15.1 D15.2 J2.1(N1) J4.1(N1) J6.1(N1) J8.1(N1) J14.2 J14.3 J14.4 J14.5(SH4) J15.2 J15.3 J15.4 J15.5(SH4) J17.2 J17.3 J17.4 J17.5(SH4) J19.2 J19.3 J19.4 J19.5(SH4) Q2.2 Q2.4 Q2.6(S3) Q3.2 Q3.4 Q3.6(S3) Q6.2 Q6.4 Q6.6(S3) Q7.2 Q7.4 Q7.6(S3) R72.2(N2) R75.2(N2) TP4.1(N1) TP25.1(N1) TP34.1(N1) TP35.1(N1) U1.11 U2.11
INTVCC_1: C21.1 R25.2(N2) R26.2(N2) R27.2(N2) TP14.1(N1) U1.9
INTVCC_2: C54.1 R55.2(N2) R56.2(N2) R57.2(N2) TP39.1(N1) U2.9
ITH_1: C14.1 R4.1 R12.1 TP10.1(N1) U1.22
ITH_2: C47.1 R4.2(N2) R42.1 TP27.1(N1) U2.22
RUN_1: C13.1 R2.1 R7.2(N2) R8.2(N2) TP5.1(N1) U1.10
RUN_2: C46.1 R2.2(N2) R37.2(N2) R38.2(N2) TP30.1(N1) U2.10
SS_1: C11.1 R3.1 TP9.1(N1) U1.20
SS_2: C44.1 R3.2(N2) TP26.1(N1) U2.20
SYNC_1: TP7.1(N1) U1.30
SYNC_2: R1.2(N2) TP32.1(N1) U2.30
UNNAMED_1_ADLTC7878V2_I139_BG1: R10.2(N2) U1.1
UNNAMED_1_ADLTC7878V2_I139_BG2: R28.2(N2) U1.12
UNNAMED_1_ADLTC7878V2_I139_BO_1: C19.2(N2) D8.C R79.2(N2) TP48.1(N1) U1.15
UNNAMED_1_ADLTC7878V2_I139_BOOS: C16.1 D5.C R78.2(N2) TP28.1(N1) U1.46
UNNAMED_1_ADLTC7878V2_I139_CSN: R29.1 TP11.1(N1) U1.35
UNNAMED_1_ADLTC7878V2_I139_CSP: C22.1 R31.1 TP16.1(N1) U1.34
UNNAMED_1_ADLTC7878V2_I139_FREQ: R18.1 U1.28
UNNAMED_1_ADLTC7878V2_I139_IS_1: C17.1 R17.1 R21.1 U1.43
UNNAMED_1_ADLTC7878V2_I139_IS_2: C17.2(N2) C18.1 R13.2(N2) R17.2(N2) R19.2(N2) U1.42
UNNAMED_1_ADLTC7878V2_I139_ISNS: C18.2(N2) R16.2(N2) R21.2(N2) R23.2(N2) U1.41
UNNAMED_1_ADLTC7878V2_I139_MODE: R22.1 R26.1 U1.26
UNNAMED_1_ADLTC7878V2_I139_PGOO: R27.1 TP15.1(N1) U1.19
UNNAMED_1_ADLTC7878V2_I139_PHAS: R24.1 R25.1 U1.27
UNNAMED_1_ADLTC7878V2_I139_SETC: R20.1 U1.31
UNNAMED_1_ADLTC7878V2_I139_TG1: R9.2(N2) U1.47
UNNAMED_1_ADLTC7878V2_I139_TG2: R30.2(N2) U1.14
UNNAMED_1_ADLTC7878V2_I139_VIN: C12.1 R69.2(N2) U1.4
UNNAMED_1_ADLTC7878V2_I139_VOUT: R70.2(N2) R71.1 U1.38(VOUT)
UNNAMED_1_CAP_I38_N1: C15.1 R12.2(N2)
UNNAMED_1_CAP_I100_N2: C22.2(N2) R29.2(N2) R32.1 TP13.1(N1)
UNNAMED_1_NCTESTPAD_I113_N1: R34.2(N2) R35.1 TP20.1(N1)
UNNAMED_1_RES_I72_N1: J18.1 Q1.1 R9.1
UNNAMED_1_RES_I73_N1: J19.1 Q2.1 R10.1
UNNAMED_1_RES_I87_N1: J17.1 Q3.1 R28.1
UNNAMED_1_RES_I115_N1: J12.1 Q4.1 R30.1
UNNAMED_2_ADLTC7878V2_I124_BG1: R40.2(N2) U2.1
UNNAMED_2_ADLTC7878V2_I124_BG2: R58.2(N2) U2.12
UNNAMED_2_ADLTC7878V2_I124_BO_1: C49.1 D12.C R80.2(N2) TP49.1(N1) U2.46
UNNAMED_2_ADLTC7878V2_I124_BOOS: C52.2(N2) D11.C R81.2(N2) TP52.1(N1) U2.15
UNNAMED_2_ADLTC7878V2_I124_CSN: R59.1 TP53.1(N1) U2.35
UNNAMED_2_ADLTC7878V2_I124_CSP: C55.1 R61.1 TP41.1(N1) U2.34
UNNAMED_2_ADLTC7878V2_I124_FREQ: R48.1 U2.28
UNNAMED_2_ADLTC7878V2_I124_IS_1: C50.2(N2) C51.1 R43.2(N2) R47.2(N2) R49.2(N2) U2.42
UNNAMED_2_ADLTC7878V2_I124_IS_2: C51.2(N2) R46.2(N2) R51.2(N2) R53.2(N2) U2.41
UNNAMED_2_ADLTC7878V2_I124_ISNS: C50.1 R47.1 R51.1 U2.43
UNNAMED_2_ADLTC7878V2_I124_ITHB: C68.1 R41.2(N2) R76.1 U2.21
UNNAMED_2_ADLTC7878V2_I124_MODE: R52.1 R56.1 U2.26
UNNAMED_2_ADLTC7878V2_I124_PGOO: R57.1 TP40.1(N1) U2.19
UNNAMED_2_ADLTC7878V2_I124_PHAS: R54.1 R55.1 U2.27
UNNAMED_2_ADLTC7878V2_I124_SETC: R50.1 U2.31
UNNAMED_2_ADLTC7878V2_I124_TG1: R39.2(N2) U2.47
UNNAMED_2_ADLTC7878V2_I124_TG2: R60.2(N2) U2.14
UNNAMED_2_ADLTC7878V2_I124_VIN: C45.1 R6.2(N2) U2.4
UNNAMED_2_ADLTC7878V2_I124_VOUT: R67.2(N2) R68.1 U2.38(VOUT)
UNNAMED_2_CAP_I32_N1: C48.1 R42.2(N2)
UNNAMED_2_CAP_I92_N2: C55.2(N2) R59.2(N2) R62.1 TP38.1(N1)
UNNAMED_2_NCTESTPAD_I104_N1: R64.2(N2) R65.1 TP45.1(N1)
UNNAMED_2_RES_I63_N1: J13.1 Q5.1 R39.1
UNNAMED_2_RES_I64_N1: J14.1 Q6.1 R40.1
UNNAMED_2_RES_I106_N1: J16.1 Q8.1 R60.1
VFB_1: R5.1 R35.2(N2) R36.1 TP18.1(N1) U1.25
VFB_2: R5.2(N2) R65.2(N2) R66.1 TP43.1(N1) U2.25
VOUT: C24.1 C25.1 C26.1 C27.1 C28.1 C29.1 C30.1 C31.1 C32.P C33.P C57.1 C58.1 C59.1 C60.1 C61.1 C62.1 C63.1 C64.1 C65.P C66.P C77.1 C78.1 C79.1 C80.1 C81.1 C82.1 C83.1 C84.1 C85.P C86.P C95.1 C96.1 C97.1 C98.1 C99.1 C100.1 C101.1 C102.1 C103.P C104.P C178.P C179.P C182.P C183.P C196.1 C197.1 C198.1 C199.1 C208.P C209.P C212.P C213.P D14.3(C) D16.3(C) J3.1(N1) J7.1(N1) Q4.3 Q4.5 Q4.7 Q8.3 Q8.5 Q8.7 R31.2(N2) R32.2(N2) R33.1 R33.2(N2) R34.1 R61.2(N2) R62.2(N2) R63.1 R63.2(N2) R64.1 R68.2(N2) R71.2(N2) R190.1 R190.2(N2) R191.1 R191.2(N2) TP19.1(N1) TP22.1(N1) TP44.1(N1)

Pads without a net: P1 1; P2 1; P3 1; P4 1; P5 1; P6 1; P7 1; P8 1; U1 2 3 5 6 13 17 18 23 32 33 36 37 39 40 44 48; U2 2 3 5 6 13 17 18 23 32 33 36 37 39 40 44 48

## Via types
v1: diameter 0.508, hole 0.254, TOP to BOTTOM, 571 vias
v2: diameter 0.356, hole 0.203, TOP to BOTTOM, 272 vias
v3: diameter 0.305, hole 0.152, TOP to BOTTOM, 88 vias
v4: diameter 0.61, hole 0.305, TOP to BOTTOM, 1157 vias

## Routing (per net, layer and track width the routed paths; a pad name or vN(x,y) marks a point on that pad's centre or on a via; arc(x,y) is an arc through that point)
SGND: length 218.4
  TOP w0.254: v1(93.47,88.51) R48.2 ; TP24.1 v3(115.44,81.92) ; TP46.1 99.64,87.81 R66.2 v1(97.54,88.39) ; TP21.1 99.64,176.71 R36.2 v1(97.54,177.29) ; C14.2 v1(100.2,172.09) C15.2 ; R18.2 v1(93.47,177.55) ; TP3.1 v3(115.44,171.45) ; v1(94.87,162.31) 94.69,162.12 94.36,162.12 C21.2 ; C11.2 99.62,170.49 v1(99.69,170.56) ; C13.2 R8.1
  TOP w0.381: C44.2 99.69,81.22 v1(99.69,81.66) 99.69,82.1 C68.2 ; C47.2 v1(100.2,83.19) C48.2
  TOP w0.508: R73.2 v1(102.49,170.05) ; R76.2 v3(102.43,81.15)
  LAYER_4 w1.27: TP31.1 12.83,45.72 41.78,74.68 59.37,74.68 71.69,87 86.23,87 91.31,81.92 v1(91.47,81.92) ; v1(91.47,170.81) 91.12,170.81 86.17,175.77 34.48,175.77 27.62,168.91 TP6.1
  LAYER_5 w0.381: v3(115.44,171.45) 113.79,169.8 111.38,169.8 ; 111.25,80.52 114.05,80.52 v3(115.44,81.92)
  vias: v1(91.44,170.18) v1(91.44,81.28) v1(91.47,169.54) v1(91.47,168.91) v1(91.47,168.28) v1(91.47,80.64) v1(91.47,80.01) v1(91.47,79.38) v1(92.1,170.81) v1(92.1,170.18) v1(92.1,169.54) v1(92.1,168.91) v1(92.1,168.28) v1(92.1,81.92) v1(92.1,81.28) v1(92.1,80.64) v1(92.1,80.01) v1(92.1,79.38) v1(92.74,170.81) v1(92.74,170.18) v1(92.74,169.54) v1(92.74,168.91) v1(92.74,168.28) v1(92.74,81.92) v1(92.74,81.28) v1(92.74,80.64) v1(92.74,80.01) v1(92.74,79.38) v1(93.37,170.81) v1(93.37,170.18) v1(93.37,169.54) v1(93.37,168.91) v1(93.37,168.28) v1(93.37,81.92) v1(93.37,81.28) v1(93.37,80.64) v1(93.37,80.01) v1(93.37,79.38) v1(94.01,170.81) v1(94.01,170.18) v1(94.01,169.54) v1(94.01,168.91) v1(94.01,168.28) v1(94.01,81.92) v1(94.01,81.28) v1(94.01,80.64) v1(94.01,80.01) v1(94.01,79.38) v1(94.87,73.34) v1(95.89,162.31) v1(95.89,73.34) v3(95,176.97) v3(95,88.07)
VIN: length 66.8
  TOP w0.254: R6.1 v1(89.79,72.9) ; R7.1 v1(97.41,161.8) 97.44,161.77 ; R69.1 v1(89.79,161.8)
  TOP w0.381: R74.1 99.63,173.1 v3(100.01,173.48) ; v3(100.08,84.58) 99.69,84.2 R77.1
  TOP w0.508: R37.1 v1(97.41,72.83)
  LAYER_3 w0.254: v1(97.41,161.8) 96.52,160.91 91.31,160.91 90.42,161.8 v1(89.79,161.8) 89.6,161.61 v1(89.6,159.38) ; v1(89.6,70.48) 89.6,72.71 v1(89.79,72.9) 90.17,72.9 91.19,71.88 96.46,71.88 v1(97.41,72.83)
  LAYER_5 w0.254: v1(97.41,72.83) 99.38,72.83 103.89,77.34 103.89,84.33 102.62,85.6 100.71,85.6 100.08,84.96 v3(100.08,84.58) ; v3(100.01,173.48) 100.01,173.93 100.71,174.62 103.12,174.62 103.89,173.86 103.89,166.37 101.73,164.21 99.19,164.21 97.41,162.43 v1(97.41,161.8)
  vias: v1(64.14,160.66) v1(64.14,71.75) v1(64.77,160.66) v1(64.77,149.86) v1(64.77,71.75) v1(64.77,60.96) v1(65.41,160.66) v1(65.41,149.86) v1(65.41,71.75) v1(65.41,60.96) v1(66.04,149.86) v1(66.04,60.96) v1(67.31,160.66) v1(67.31,71.75) v1(67.94,160.66) v1(67.94,149.86) v1(67.94,71.75) v1(67.94,60.96) v1(68.58,160.66) v1(68.58,149.86) v1(68.58,71.75) v1(68.58,60.96) v1(69.22,149.86) v1(69.22,60.96) v1(70.48,160.66) v1(70.48,71.75) v1(71.12,160.66) v1(71.12,149.86) v1(71.12,71.75) v1(71.12,60.96) v1(71.75,160.66) v1(71.75,149.86) v1(71.75,71.75) v1(71.75,60.96) v1(72.39,149.86) v1(72.39,60.96) v1(73.03,157.48) v1(73.03,156.21) v1(73.03,154.94) v1(73.03,153.67) v1(73.03,68.58) v1(73.03,67.31) v1(73.03,66.04) v1(73.03,64.77) v1(75.56,61.21) v1(75.56,60.58) v1(75.69,150.11) v1(75.69,149.48) v1(76.2,61.21) v1(76.2,60.58) v1(76.33,150.11) v1(76.33,149.48) v1(76.83,61.21) v1(76.83,60.58) v1(76.96,150.11) v1(76.96,149.48) v1(77.47,157.48) v1(77.47,156.21) v1(77.47,154.94) v1(77.47,153.67) v1(77.47,68.58) v1(77.47,67.31) v1(77.47,66.04) v1(77.47,64.77) v1(77.47,61.21) v1(77.47,60.58) v1(77.6,150.11) v1(77.6,149.48) v1(89.6,158.12) v1(89.6,156.84) v1(89.6,155.57) v1(89.6,154.31) v1(89.6,153.03) v1(89.6,151.76) v1(89.6,69.22) v1(89.6,67.94) v1(89.6,66.67) v1(89.6,65.41) v1(89.6,64.14) v1(89.6,62.87) v1(90.17,156.84) v1(90.17,155.57) v1(90.17,154.31) v1(90.17,153.03) v1(90.17,67.94) v1(90.17,66.67) v1(90.17,65.41) v1(90.17,64.14) v2(78.61,156.84) v2(78.61,155.13) v2(78.61,153.35) v2(78.61,67.94) v2(78.61,66.24) v2(78.61,64.45) v2(79.12,156.84) v2(79.12,155.13) v2(79.12,153.35) v2(79.12,67.94) v2(79.12,66.24) v2(79.12,64.45) v2(79.76,156.84) v2(79.76,155.13) v2(79.76,153.35) v2(79.76,67.94) v2(79.76,66.24) v2(79.76,64.45) v2(80.26,156.84) v2(80.26,155.13) v2(80.26,153.35) v2(80.26,67.94) v2(80.26,66.24) v2(80.26,64.45) v2(80.9,156.84) v2(80.9,155.13) v2(80.9,153.35) v2(80.9,67.94) v2(80.9,66.24) v2(80.9,64.45) v2(81.41,156.84) v2(81.41,155.13) v2(81.41,153.35) v2(81.41,67.94) v2(81.41,66.24) v2(81.41,64.45) v4(5.08,127) v4(5.08,121.92) v4(5.08,106.68) v4(10.16,147.32) v4(10.16,121.92) v4(10.16,106.68) v4(15.24,147.32) v4(15.24,142.24) v4(15.24,127) v4(15.24,121.92) v4(15.24,106.68) v4(20.32,157.48) v4(20.32,152.4) v4(20.32,147.32) v4(20.32,142.24) v4(20.32,137.16) v4(20.32,132.08) v4(20.32,127) v4(20.32,121.92) v4(20.32,116.84) v4(20.32,111.76) v4(20.32,106.68) v4(20.32,101.6) v4(20.32,96.52) v4(20.32,91.44) v4(20.32,86.36) v4(20.32,81.28) v4(20.32,76.2) v4(20.32,71.12) v4(20.32,66.04) v4(20.32,60.96) v4(20.32,55.88) v4(25.4,157.48) v4(25.4,152.4) v4(25.4,147.32) v4(25.4,142.24) v4(25.4,137.16) v4(25.4,132.08) v4(25.4,127) v4(25.4,121.92) v4(25.4,116.84) v4(25.4,111.76) v4(25.4,106.68) v4(25.4,101.6) v4(25.4,96.52) v4(25.4,91.44) v4(25.4,86.36) v4(25.4,81.28) v4(25.4,76.2) v4(25.4,71.12) v4(25.4,66.04) v4(25.4,60.96) v4(25.4,55.88) v4(30.48,157.48) v4(30.48,152.4) v4(30.48,147.32) v4(30.48,142.24) v4(30.48,137.16) v4(30.48,132.08) v4(30.48,127) v4(30.48,121.92) v4(30.48,116.84) v4(30.48,111.76) v4(30.48,106.68) v4(30.48,101.6) v4(30.48,96.52) v4(30.48,91.44) v4(30.48,86.36) v4(30.48,81.28) v4(30.48,76.2) v4(30.48,71.12) v4(30.48,66.04) v4(30.48,60.96) v4(30.48,55.88) v4(35.56,157.48) v4(35.56,152.4) v4(35.56,147.32) v4(35.56,142.24) v4(35.56,137.16) v4(35.56,132.08) v4(35.56,127) v4(35.56,121.92) v4(35.56,116.84) v4(35.56,111.76) v4(35.56,106.68) v4(35.56,101.6) v4(35.56,96.52) v4(35.56,91.44) v4(35.56,86.36) v4(35.56,81.28) v4(35.56,76.2) v4(35.56,71.12) v4(35.56,66.04) v4(35.56,60.96) v4(35.56,55.88) v4(40.64,157.48) v4(40.64,152.4) v4(40.64,147.32) v4(40.64,71.12) v4(40.64,66.04) v4(40.64,60.96) v4(40.64,55.88) v4(44.32,160.02) v4(44.32,158.12) v4(44.32,156.21) v4(44.32,149.86) v4(44.32,147.96) v4(44.32,146.05) v4(44.32,71.25) v4(44.32,69.34) v4(44.32,67.44) v4(44.32,60.96) v4(44.32,59.05) v4(44.32,57.15) v4(45.72,152.4) v4(47.12,160.02) v4(47.12,158.12) v4(47.12,156.21) v4(47.12,149.86) v4(47.12,147.96) v4(47.12,146.05) v4(47.12,71.25) v4(47.12,69.34) v4(47.12,67.44) v4(47.12,60.96) v4(47.12,59.05) v4(47.12,57.15) v4(50.8,157.48) v4(50.8,152.4) v4(50.8,66.04) v4(50.8,60.96) v4(55.75,160.02) v4(55.75,158.12) v4(55.75,156.21) v4(55.75,149.86) v4(55.75,147.96) v4(55.75,146.05) v4(55.75,71.25) v4(55.75,69.34) v4(55.75,67.44) v4(55.75,60.96) v4(55.75,59.05) v4(55.75,57.15) v4(55.88,152.4) v4(58.55,160.02) v4(58.55,158.12) v4(58.55,156.21) v4(58.55,149.86) v4(58.55,147.96) v4(58.55,146.05) v4(58.55,71.25) v4(58.55,69.34) v4(58.55,67.44) v4(58.55,60.96) v4(58.55,59.05) v4(58.55,57.15) v4(60.96,157.48) v4(60.96,152.4) v4(60.96,66.04) v4(60.96,60.96) v4(71.12,157.48) v4(71.12,152.4) v4(71.12,66.04)
_N4: length 6.5
  TOP w0.254: U1.21 97.13,170.79 97.41,171.07 v3(98.04,171.07) C67.1 ; R11.2 v3(100.78,170.56) R73.1
  LAYER_4 w0.254: v3(98.04,171.07) 98.17,171.2 100.15,171.2 v3(100.78,170.56)
_N10: length 16.4
  TOP w0.254: v3(102.36,171.07) R11.1 ; TP2.1 116.08,176.02 v3(115.44,176.02)
  LAYER_6 w0.254: v3(102.36,171.07) 107.38,171.07 110.17,173.86 113.28,173.86 v3(115.44,176.02)
_N12: length 3.7
  TOP w0.254: R72.1 R74.2 96.97,173.1 U1.24
_N77: length 9.8
  TOP w0.508: R58.1 99.31,76.45 100.84,74.93 v1(100.84,69.98) 100.84,68.98 100.96,68.85
  BOTTOM w0.508: J15.1 v1(100.84,69.98)
_N135: length 16.1
  TOP w0.254: TP23.1 v3(115.44,86.49)
  TOP w0.508: R41.1 v3(102.49,82.17)
  LAYER_6 w0.254: v3(115.44,86.49) 114.05,86.49 109.98,82.42 102.74,82.42 v3(102.49,82.17)
_N140: length 3.7
  TOP w0.254: R77.2 97.54,84.2 96.73,83.4 U2.24
  TOP w0.508: R75.1 R77.2
_N144: length 1.4
  TOP w0.254: D3.C 84.02,75.26 R80.1
_N145: length 1.5
  TOP w0.254: D4.C 104.05,77.34 104.25,77.54 R81.1
_N183: length 1.5
  TOP w0.254: D2.C 104.05,166.24 104.25,166.44 R79.1
_N184: length 1.4
  TOP w0.254: R78.1 82.73,164.21 D1.C
_N327: length 96.8
  TOP w0.254: v1(90.93,133.6) 90.93,133.61 L1.2 ; R14.2 v1(83.31,142.88) ; R19.1 v1(83.31,169.54) ; R16.1 v1(83.19,170.81)
  LAYER_6 w0.254: v1(83.19,170.81) 84.07,169.93 84.07,169.16 83.31,168.4 81.92,168.4 75.95,162.43 75.95,152.53 77.09,151.38 78.11,151.38 79.44,150.05 79.44,144.59 81.03,143 83.19,143 v1(83.31,142.88) ; v1(83.31,169.54) 82.68,169.54 81.79,170.43 81.03,170.43 74.55,163.96 74.55,144.65 80.64,138.56 88.01,138.56 90.42,136.14 90.42,134.11 v1(90.93,133.6)
  BOTTOM w0.254: R14.2 v1(83.31,142.88)
  vias: v1(81.28,140.97) v1(81.28,140.34) v1(82.55,140.97) v1(82.55,140.34) v1(83.82,140.97) v1(83.82,140.34) v1(85.09,140.97) v1(85.09,140.34) v1(86.11,135.89) v1(86.11,134.62) v1(86.11,133.35) v1(86.11,132.08) v1(86.74,135.89) v1(86.74,134.62) v1(86.74,133.35) v1(86.74,132.08)
_N339: length 96.9
  TOP w0.254: L2.2 88.27,44.7 v1(90.93,44.7) ; v1(83.19,81.92) R46.1 ; v1(83.31,80.64) R49.1
  TOP w0.508: R44.2 v1(83.31,53.91)
  LAYER_6 w0.254: v1(83.31,53.91) 83.12,54.1 81.03,54.1 79.44,55.69 79.44,61.15 78.11,62.48 77.09,62.48 75.95,63.63 75.95,73.53 81.92,79.5 83.31,79.5 84.07,80.26 84.07,81.03 v1(83.19,81.92) ; v1(83.31,80.64) 82.68,80.64 81.79,81.53 81.03,81.53 74.55,75.06 74.55,55.75 80.64,49.66 88.01,49.66 90.42,47.24 90.42,45.21 v1(90.93,44.7)
  BOTTOM w0.508: v1(83.31,53.91) R44.2
  vias: v1(81.28,52.07) v1(81.28,51.44) v1(82.55,52.07) v1(82.55,51.44) v1(83.82,52.07) v1(83.82,51.44) v1(85.09,52.07) v1(85.09,51.44) v1(86.36,46.99) v1(86.36,45.72) v1(86.36,44.45) v1(86.36,43.18) v1(87,46.99) v1(87,45.72) v1(87,44.45) v1(87,43.18)
_N377: length 99.3
  TOP w0.254: U2.16 97.84,79.4 C52.1 98.55,78.74 99.25,79.44 101.07,79.44 101.13,79.5 101.26,79.38 ; TP51.1 v3(111,86.36) ; L2.1 v1(95.63,44.71) 95.63,44.7 ; R53.1 v1(83.19,83.19)
  TOP w0.508: C52.1 v1(98.5,79.19)
  LAYER_2 w0.508: v1(98.5,79.19) 98.5,78.03 99.06,77.47 99.57,77.47 102.49,74.55 102.49,73.41 104.78,71.12 v2(104.78,69.34) v2(104.78,68.9)
  LAYER_4 w0.254: v1(98.5,79.19) 99.13,79.19 99.31,79.38 100.71,79.38 101.22,79.88 104.52,79.88 v3(111,86.36)
  LAYER_6 w0.254: v1(95.63,44.71) 92.08,44.71 91.44,44.07 90.55,44.07 89.92,44.7 89.92,46.99 87.76,49.15 80.39,49.15 74.04,55.5 74.04,75.31 80.9,82.17 81.79,82.17 82.8,83.19 v1(83.19,83.19)
  vias: v1(98.93,59.44) v1(99.69,62.23) v1(99.69,61.59) v1(99.69,57.15) v1(99.69,56.52) v1(99.69,46.99) v1(99.69,45.72) v1(99.69,44.45) v1(99.69,43.18) v1(100.2,59.44) v1(100.33,46.99) v1(100.33,45.72) v1(100.33,44.45) v1(100.33,43.18) v1(100.97,62.23) v1(100.97,61.59) v1(100.97,57.15) v1(100.97,56.52) v1(101.47,59.44) v1(102.23,62.23) v1(102.23,61.59) v1(102.23,57.15) v1(102.23,56.52) v1(102.74,59.44) v1(103.5,62.23) v1(103.5,61.59) v1(103.5,57.15) v1(103.5,56.52) v2(98.3,67.94) v2(98.3,66.24) v2(98.3,64.38) v2(98.81,67.94) v2(98.81,66.24) v2(98.81,64.38) v2(99.44,67.94) v2(99.44,66.24) v2(99.44,64.38) v2(99.95,67.94) v2(99.95,66.24) v2(99.95,64.38) v2(100.58,67.94) v2(100.58,66.24) v2(100.58,64.38) v2(101.09,67.94) v2(101.09,66.24) v2(101.09,64.38) v2(103.38,69.34) v2(103.38,68.9) v2(103.38,67.09) v2(103.38,65.39) v2(103.89,67.09) v2(103.89,65.39) v2(104.52,67.09) v2(104.52,65.39) v2(105.03,67.09) v2(105.03,65.39) v2(105.66,67.09) v2(105.66,65.39) v2(106.17,67.09) v2(106.17,65.39)
_N381: length 100
  TOP w0.254: TP47.1 v3(111,175.9) ; R23.1 v1(83.19,172.09) ; L1.1 v1(95.76,133.61) 95.76,133.6 ; 101.26,168.28 D8.A 99.19,168.28 98.56,167.64 C19.1 98.43,167.64 97.78,168.3 U1.16
  TOP w0.508: C19.1 v1(98.5,168.09)
  LAYER_2 w0.508: v2(104.65,157.86) v2(104.65,158.24) 104.65,160.15 102.49,162.31 102.49,164.34 101.09,165.74 100.2,165.74 99.57,166.37 98.81,166.37 98.5,166.68 v1(98.5,168.09)
  LAYER_4 w0.254: v3(111,175.9) 104.14,169.04 101.78,169.04 101.15,168.4 98.81,168.4 v1(98.5,168.09)
  LAYER_6 w0.254: v1(83.19,172.09) 82.8,172.09 81.79,171.07 80.9,171.07 74.04,164.21 74.04,144.4 80.39,138.05 87.76,138.05 89.92,135.89 89.92,133.6 90.55,132.97 91.44,132.97 92.08,133.61 v1(95.76,133.61)
  vias: v1(99.06,151.13) v1(99.06,150.5) v1(99.06,146.05) v1(99.06,145.41) v1(99.69,135.89) v1(99.69,134.62) v1(99.69,133.35) v1(99.69,132.08) v1(100.33,151.13) v1(100.33,150.5) v1(100.33,146.05) v1(100.33,145.41) v1(100.33,135.89) v1(100.33,134.62) v1(100.33,133.35) v1(100.33,132.08) v1(101.6,151.13) v1(101.6,150.5) v1(101.6,146.05) v1(101.6,145.41) v1(102.87,151.13) v1(102.87,150.5) v1(102.87,146.05) v1(102.87,145.41) v2(98.3,156.87) v2(98.3,155.17) v2(98.3,153.31) v2(98.81,156.87) v2(98.81,155.17) v2(98.81,153.31) v2(99.44,156.87) v2(99.44,155.17) v2(99.44,153.31) v2(99.95,156.87) v2(99.95,155.17) v2(99.95,153.31) v2(100.58,156.87) v2(100.58,155.17) v2(100.58,153.31) v2(101.09,156.87) v2(101.09,155.17) v2(101.09,153.31) v2(103.38,156.02) v2(103.38,154.32) v2(103.5,158.24) v2(103.5,157.86) v2(103.89,156.02) v2(103.89,154.32) v2(104.52,156.02) v2(104.52,154.32) v2(105.03,156.02) v2(105.03,154.32) v2(105.66,156.02) v2(105.66,154.32) v2(106.17,156.02) v2(106.17,154.32)
_N399: length 70.3
  TOP w0.254: D12.A 85.64,78.49 C49.2 86.11,78.49 87.02,79.4 U2.45 ; v1(83.82,78.99) 83.82,79.56 R43.1 ; TP50.1 v3(75.06,83.82)
  TOP w0.508: C49.2 86.05,78.03 v1(86.11,77.98) ; R44.1 v1(83.31,55.12)
  LAYER_2 w0.508: v1(86.11,77.98) 85.85,77.72 85.85,76.71 86.23,76.33 86.23,73.03 84.71,71.5 81.41,71.5 80.01,70.1 v2(80.01,69.34) v2(80.01,68.9)
  LAYER_4 w0.254: v1(86.11,77.98) 80.9,77.98 v3(75.06,83.82)
  LAYER_6 w0.254: v1(83.31,55.12) 82.8,54.61 81.28,54.61 79.95,55.94 79.95,61.4 78.36,62.99 77.34,62.99 76.45,63.88 76.45,73.28 82.17,78.99 v1(83.82,78.99)
  BOTTOM w0.508: v1(83.31,55.12) R44.1
  vias: v1(81.28,57.4) v1(81.28,56.77) v1(82.55,57.4) v1(82.55,56.77) v1(83.82,57.4) v1(83.82,56.77) v1(85.09,57.4) v1(85.09,56.77) v2(78.61,69.34) v2(78.61,68.9) v2(78.61,67.12) v2(78.61,65.41) v2(79.12,67.12) v2(79.12,65.41) v2(79.76,67.12) v2(79.76,65.41) v2(80.26,67.12) v2(80.26,65.41) v2(80.9,67.12) v2(80.9,65.41) v2(81.41,67.12) v2(81.41,65.41) v2(83.69,67.94) v2(83.69,66.23) v2(83.69,64.45) v2(84.2,67.94) v2(84.2,66.23) v2(84.2,64.45) v2(84.84,67.94) v2(84.84,66.23) v2(84.84,64.45) v2(85.34,67.94) v2(85.34,66.23) v2(85.34,64.45) v2(85.98,67.94) v2(85.98,66.23) v2(85.98,64.45) v2(86.49,67.94) v2(86.49,66.23) v2(86.49,64.45)
_N400: length 69.8
  TOP w0.254: v1(83.82,167.89) 83.82,168.02 83.89,168.09 R13.1 ; U1.45 87.09,168.3 C16.2 85.76,167.39 D5.A ; TP29.1 v3(75.69,172.72) ; R14.1 v1(83.31,143.76)
  TOP w0.508: v1(86.17,166.88) 86.18,166.89 C16.2
  LAYER_2 w0.508: v2(80.01,157.8) v2(80.01,158.24) 80.01,159 80.77,159.77 82.04,159.77 82.55,160.27 84.33,160.27 86.17,162.12 86.17,165.16 85.98,165.35 85.98,166.69 v1(86.17,166.88)
  LAYER_4 w0.254: v3(75.69,172.72) 81.53,166.88 v1(86.17,166.88)
  LAYER_6 w0.254: v1(83.31,143.76) 83.06,143.51 81.28,143.51 79.95,144.84 79.95,150.3 78.36,151.89 77.34,151.89 76.45,152.78 76.45,162.18 82.17,167.89 v1(83.82,167.89)
  BOTTOM w0.254: R14.1 v1(83.31,143.76)
  vias: v1(81.28,151.13) v1(81.28,150.5) v1(81.28,146.3) v1(81.28,145.67) v1(82.55,151.13) v1(82.55,150.5) v1(82.55,146.3) v1(82.55,145.67) v1(83.82,151.13) v1(83.82,150.5) v1(83.82,146.3) v1(83.82,145.67) v1(85.09,151.13) v1(85.09,150.5) v1(85.09,146.3) v1(85.09,145.67) v2(78.61,158.24) v2(78.61,157.8) v2(78.61,156.02) v2(78.61,154.31) v2(79.12,156.02) v2(79.12,154.31) v2(79.76,156.02) v2(79.76,154.31) v2(80.26,156.02) v2(80.26,154.31) v2(80.9,156.02) v2(80.9,154.31) v2(81.41,156.02) v2(81.41,154.31) v2(83.69,156.84) v2(83.69,155.13) v2(83.69,153.35) v2(84.2,156.84) v2(84.2,155.13) v2(84.2,153.35) v2(84.84,156.84) v2(84.84,155.13) v2(84.84,153.35) v2(85.34,156.84) v2(85.34,155.13) v2(85.34,153.35) v2(85.98,156.84) v2(85.98,155.13) v2(85.98,153.35) v2(86.49,156.84) v2(86.49,155.13) v2(86.49,153.35)
CLKOUT_1: length 206.1
  TOP w0.254: U1.29 93.46,173.98 v3(93.47,173.99)
  LAYER_4 w0.254: TP8.1 163.64,174.82 124.4,174.82 121.79,177.42 108.84,177.42 106.68,175.26 99.19,175.26 97.6,173.67 93.79,173.67 v3(93.47,173.99)
  LAYER_5 w0.254: v3(93.47,91.3) 92.99,91.77 87.43,91.77 75.05,104.15 75.05,170.31 79.92,175.18 88.18,175.18 89.93,173.42 92.91,173.42 v3(93.47,173.99)
CLKOUT_2: length 114.3
  TOP w0.254: U2.29 93.46,85.08 v3(93.47,85.09)
  LAYER_4 w0.254: v3(93.47,85.09) 93.6,84.96 97.79,84.96 99.19,86.36 108.58,86.36 110.24,88.01 126.24,88.01 127.89,86.36 139.95,86.36 158.75,67.56 158.75,57.59 178.44,37.91 TP33.1
DRVCC_1: length 47.5
  TOP w0.254: v3(102.23,166.5) 101.35,166.5 D2.A ; 92.08,163.5 C23.1 92.08,163.96 v3(92.01,164.02) 92.96,164.97 U1.7 ; TP17.1 v3(71.18,168.91) ; D1.A v3(85.09,164.21)
  LAYER_4 w0.254: 92.01,165.04 v3(92.01,164.02) ; 92.01,165.04 100.77,165.04 v3(102.23,166.5) ; 92.01,165.04 91.95,164.97 76.83,164.97 72.9,168.91 v3(71.18,168.91)
  LAYER_6 w0.254: v3(85.09,164.21) 90.11,164.21 90.3,164.02 v3(92.01,164.02)
DRVCC_2: length 48.1
  TOP w0.254: U2.7 92.96,76.07 v3(92.01,75.12) ; D4.A 101.35,77.6 v3(102.23,77.6) ; 92.04,75.12 92.1,75.06 92.1,74.63 92.08,74.6 ; D3.A v3(85.09,75.31) ; TP42.1 v3(70.61,80.01)
  LAYER_4 w0.254: v3(102.23,77.6) 100.71,76.07 92.01,76.07 ; 92.01,76.07 74.55,76.07 v3(70.61,80.01) ; 92.01,76.07 v3(92.01,75.12)
  LAYER_6 w0.254: v3(92.01,75.12) 91.82,75.31 v3(85.09,75.31)
EXTVCC: length 289.5
  LAYER_6 w0.254: v3(65.53,172.72) 65.41,172.72 63.75,171.07 37.34,171.07 28.07,161.8 28.07,50.29 6.99,29.21 TP36.1 8,27.43 19.3,27.43 38.23,46.35 38.23,78.36 43.69,83.82 v3(66.17,83.82)
  BOTTOM w0.254: R82.2 v3(65.53,172.72) ; R83.2 v3(66.17,83.82)
EXTVCC_1: length 33.6
  TOP w0.254: U1.8 93.47,166.08 93.47,164.47 93.03,164.02 v3(92.96,164.02) ; TP12.1 v3(71.18,172.72)
  TOP w0.381: R70.1 v3(85.09,173.23)
  LAYER_6 w0.254: 71.18,172.78 v3(71.18,172.72) 72.33,173.86 76.71,173.86 77.34,173.23 v3(85.09,173.23) 86.74,171.58 87.38,171.58 88.27,170.69 88.27,168.78 92.96,164.08 v3(92.96,164.02)
  BOTTOM w0.254: R82.1 v3(71.18,172.72)
EXTVCC_2: length 34
  TOP w0.254: R67.1 v3(85.09,84.33) ; C53.1 v3(93.22,75.31) 93.46,75.55 U2.8 ; TP37.1 v3(70.61,83.82)
  LAYER_6 w0.254: v3(70.61,83.82) 71.75,84.96 83.44,84.96 84.07,84.33 v3(85.09,84.33) 86.49,82.93 87.5,82.93 88.39,82.04 88.39,79.88 92.96,75.31 v3(93.22,75.31)
  BOTTOM w0.254: R83.1 v3(70.61,83.82)
GROUND: length 4.4
  TOP w0.254: v1(99.57,174.62) 99.57,174.17 R72.2 ; C95.2 109.22,70.94 v1(109.22,70.48) ; v1(92.58,161.93) 92.66,162 C20.2 ; v1(99.57,85.72) 99.57,85.27 R75.2 ; v1(92.58,73.03) 93.14,73.03 C53.2 ; v1(91.57,161.93) 91.49,162 C12.2 ; v1(91.57,73.03) 91.01,73.03 C45.2
  vias: v1(64.14,165.74) v1(64.14,76.83) v1(64.77,165.74) v1(64.77,146.69) v1(64.77,144.78) v1(64.77,76.83) v1(64.77,57.78) v1(64.77,55.88) v1(65.41,165.74) v1(65.41,146.69) v1(65.41,144.78) v1(65.41,76.83) v1(65.41,57.78) v1(65.41,55.88) v1(66.04,146.69) v1(66.04,144.78) v1(66.04,57.78) v1(66.04,55.88) v1(67.31,165.74) v1(67.31,76.83) v1(67.94,165.74) v1(67.94,146.69) v1(67.94,144.78) v1(67.94,76.83) v1(67.94,57.78) v1(67.94,55.88) v1(68.58,165.74) v1(68.58,146.69) v1(68.58,144.78) v1(68.58,76.83) v1(68.58,57.78) v1(68.58,55.88) v1(69.22,146.69) v1(69.22,144.78) v1(69.22,57.78) v1(69.22,55.88) v1(70.48,165.74) v1(70.48,76.83) v1(71.12,165.74) v1(71.12,146.69) v1(71.12,144.78) v1(71.12,76.83) v1(71.12,57.78) v1(71.12,55.88) v1(71.75,165.74) v1(71.75,146.69) v1(71.75,144.78) v1(71.75,76.83) v1(71.75,57.78) v1(71.75,55.88) v1(72.39,146.69) v1(72.39,144.78) v1(72.39,57.78) v1(72.39,55.88) v1(88.14,159.38) v1(88.14,158.12) v1(88.14,156.84) v1(88.14,155.57) v1(88.14,154.31) v1(88.14,153.03) v1(88.14,151.76) v1(88.14,70.48) v1(88.14,69.22) v1(88.14,67.94) v1(88.14,66.67) v1(88.14,65.41) v1(88.14,64.14) v1(88.14,62.87) v1(89.66,60.71) v1(89.66,60.07) v1(89.66,58.8) v1(89.66,58.17) v1(95.76,60.71) v1(95.76,60.07) v1(95.76,58.8) v1(95.76,58.17) v1(109.22,159.38) v1(109.22,158.12) v1(109.22,156.84) v1(109.22,155.57) v1(109.22,154.31) v1(109.22,153.03) v1(109.22,151.76) v1(109.22,69.22) v1(109.22,67.94) v1(109.22,66.67) v1(109.22,65.41) v1(109.22,64.14) v1(109.22,62.87) v1(109.73,156.84) v1(109.73,155.57) v1(109.73,154.31) v1(109.73,153.03) v1(109.73,67.94) v1(109.73,66.67) v1(109.73,65.41) v1(109.73,64.14) v1(113.03,144.91) v1(113.03,57.91) v1(113.03,56.01) v1(113.41,165.74) v1(113.41,76.83) v1(113.67,144.91) v1(113.67,57.91) v1(113.67,56.01) v1(114.05,165.74) v1(114.05,76.83) v1(114.3,144.91) v1(114.3,57.91) v1(114.3,56.01) v1(114.68,165.74) v1(114.68,76.83) v1(116.2,144.91) v1(116.2,57.91) v1(116.2,56.01) v1(116.59,165.74) v1(116.59,76.83) v1(116.84,144.91) v1(116.84,57.91) v1(116.84,56.01) v1(117.22,165.74) v1(117.22,76.83) v1(117.47,144.91) v1(117.47,57.91) v1(117.47,56.01) v1(117.86,165.74) v1(117.86,76.83) v1(119.38,144.91) v1(119.38,57.91) v1(119.38,56.01) v1(119.76,165.74) v1(119.76,76.83) v1(120.02,144.91) v1(120.02,57.91) v1(120.02,56.01) v1(120.4,165.74) v1(120.4,76.83) v1(120.65,144.91) v1(120.65,57.91) v1(120.65,56.01) v1(121.03,165.74) v1(121.03,76.83) v1(134.24,141.22) v1(134.24,52.32) v1(134.37,165.74) v1(134.37,76.83) v1(134.87,141.22) v1(134.87,52.32) v1(135,165.74) v1(135,76.83) v1(135.51,141.22) v1(135.51,52.32) v1(135.64,165.74) v1(135.64,76.83) v2(83.69,156.02) v2(83.69,154.31) v2(83.69,67.09) v2(83.69,65.39) v2(83.76,158.24) v2(83.76,157.8) v2(83.82,69.34) v2(83.82,68.9) v2(84.2,156.02) v2(84.2,154.31) v2(84.2,67.09) v2(84.2,65.39) v2(84.84,156.02) v2(84.84,154.31) v2(84.84,67.09) v2(84.84,65.39) v2(84.96,69.34) v2(84.96,68.9) v2(85.09,158.24) v2(85.09,157.8) v2(85.34,156.02) v2(85.34,154.31) v2(85.34,67.09) v2(85.34,65.39) v2(85.98,156.02) v2(85.98,154.31) v2(85.98,67.09) v2(85.98,65.39) v2(86.49,156.02) v2(86.49,154.31) v2(86.49,67.09) v2(86.49,65.39) v2(98.3,156.02) v2(98.3,154.32) v2(98.3,69.34) v2(98.3,68.9) v2(98.3,67.09) v2(98.3,65.39) v2(98.42,158.24) v2(98.42,157.86) v2(98.81,156.02) v2(98.81,154.32) v2(98.81,67.09) v2(98.81,65.39) v2(99.44,156.02) v2(99.44,154.32) v2(99.44,67.09) v2(99.44,65.39) v2(99.69,158.24) v2(99.69,157.86) v2(99.69,69.34) v2(99.69,68.9) v2(99.95,156.02) v2(99.95,154.32) v2(99.95,67.09) v2(99.95,65.39) v2(100.58,156.02) v2(100.58,154.32) v2(100.58,67.09) v2(100.58,65.39) v2(101.09,156.02) v2(101.09,154.32) v2(101.09,67.09) v2(101.09,65.39) v4(1.65,182.25) v4(1.65,177.16) v4(1.65,172.09) v4(1.65,167) v4(1.65,161.93) v4(1.65,156.84) v4(1.65,151.76) v4(1.65,146.69) v4(1.65,141.6) v4(1.65,136.53) v4(1.65,131.44) v4(1.65,126.36) v4(1.65,121.28) v4(1.65,116.2) v4(1.65,111.12) v4(1.65,106.05) v4(1.65,100.97) v4(1.65,95.89) v4(1.65,90.81) v4(1.65,85.72) v4(1.65,80.64) v4(1.65,75.56) v4(1.65,70.48) v4(1.65,65.41) v4(1.65,60.33) v4(1.65,55.24) v4(1.65,50.16) v4(1.65,45.09) v4(1.65,40.01) v4(1.65,34.92) v4(1.65,29.84) v4(1.65,24.77) v4(1.65,19.68) v4(1.65,14.61) v4(1.65,9.53) v4(5.08,182.88) v4(5.08,177.8) v4(5.08,172.72) v4(5.08,157.48) v4(5.08,152.4) v4(5.08,101.6) v4(5.08,96.52) v4(5.08,86.36) v4(5.08,81.28) v4(5.08,76.2) v4(5.08,60.96) v4(5.08,50.8) v4(5.08,40.64) v4(5.08,35.56) v4(5.08,30.48) v4(5.08,25.4) v4(5.08,20.32) v4(5.08,15.24) v4(10.16,190.63) v4(10.16,187.96) v4(10.16,182.88) v4(10.16,177.8) v4(10.16,172.72) v4(10.16,157.48) v4(10.16,152.4) v4(10.16,101.6) v4(10.16,96.52) v4(10.16,81.28) v4(10.16,76.2) v4(10.16,60.96) v4(10.16,55.88) v4(10.16,50.8) v4(10.16,35.56) v4(10.16,30.48) v4(10.16,25.4) v4(10.16,20.32) v4(10.16,15.24) v4(10.16,10.16) v4(10.16,6.86) v4(15.24,190.63) v4(15.24,187.96) v4(15.24,182.88) v4(15.24,177.8) v4(15.24,172.72) v4(15.24,157.48) v4(15.24,152.4) v4(15.24,101.6) v4(15.24,96.52) v4(15.24,86.36) v4(15.24,81.28) v4(15.24,76.2) v4(15.24,60.96) v4(15.24,55.88) v4(15.24,50.8) v4(15.24,40.64) v4(15.24,35.56) v4(15.24,30.48) v4(15.24,25.4) v4(15.24,20.32) v4(15.24,15.24) v4(15.24,10.16) v4(15.24,6.86) v4(20.32,190.63) v4(20.32,187.96) v4(20.32,182.88) v4(20.32,177.8) v4(20.32,172.72) v4(20.32,45.72) v4(20.32,40.64) v4(20.32,35.56) v4(20.32,30.48) v4(20.32,25.4) v4(20.32,20.32) v4(20.32,15.24) v4(20.32,10.16) v4(20.32,6.86) v4(25.4,190.63) v4(25.4,187.96) v4(25.4,182.88) v4(25.4,177.8) v4(25.4,172.72) v4(25.4,50.8) v4(25.4,45.72) v4(25.4,40.64) v4(25.4,35.56) v4(25.4,30.48) v4(25.4,25.4) v4(25.4,20.32) v4(25.4,15.24) v4(25.4,10.16) v4(25.4,6.86) v4(30.48,190.63) v4(30.48,187.96) v4(30.48,182.88) v4(30.48,177.8) v4(30.48,50.8) v4(30.48,45.72) v4(30.48,40.64) v4(30.48,35.56) v4(30.48,30.48) v4(30.48,25.4) v4(30.48,20.32) v4(30.48,15.24) v4(30.48,10.16) v4(30.48,6.86) v4(35.56,190.63) v4(35.56,187.96) v4(35.56,182.88) v4(35.56,177.8) v4(35.56,172.72) v4(35.56,167.64) v4(35.56,50.8) v4(35.56,45.72) v4(35.56,40.64) v4(35.56,35.56) v4(35.56,30.48) v4(35.56,25.4) v4(35.56,20.32) v4(35.56,15.24) v4(35.56,10.16) v4(35.56,5.08) v4(40.64,190.63) v4(40.64,187.96) v4(40.64,182.88) v4(40.64,177.8) v4(40.64,172.72) v4(40.64,167.64) v4(40.64,50.8) v4(40.64,45.72) v4(40.64,40.64) v4(40.64,35.56) v4(40.64,30.48) v4(40.64,25.4) v4(40.64,20.32) v4(40.64,15.24) v4(40.64,10.16) v4(40.64,5.08) v4(40.64,1.65) v4(44.32,168.91) v4(44.32,167) v4(44.32,165.1) v4(44.32,140.97) v4(44.32,139.06) v4(44.32,137.16) v4(44.32,80.01) v4(44.32,78.11) v4(44.32,76.2) v4(44.26,52.01) v4(44.26,50.1) v4(44.26,48.2) v4(45.72,190.63) v4(45.72,187.96) v4(45.72,182.88) v4(45.72,177.8) v4(45.72,172.72) v4(45.72,132.08) v4(45.72,127) v4(45.72,121.92) v4(45.72,116.84) v4(45.72,111.76) v4(45.72,106.68) v4(45.72,101.6) v4(45.72,96.52) v4(45.72,91.44) v4(45.72,86.36) v4(45.72,45.72) v4(45.72,40.64) v4(45.72,35.56) v4(45.72,30.48) v4(45.72,25.4) v4(45.72,20.32) v4(45.72,15.24) v4(45.72,10.16) v4(45.72,5.08) v4(45.72,1.65) v4(47.12,168.91) v4(47.12,167) v4(47.12,165.1) v4(47.12,140.97) v4(47.12,139.06) v4(47.12,137.16) v4(47.12,80.01) v4(47.12,78.11) v4(47.12,76.2) v4(47.05,52.01) v4(47.05,50.1) v4(47.05,48.2) v4(50.8,190.63) v4(50.8,187.96) v4(50.8,182.88) v4(50.8,177.8) v4(50.8,172.72) v4(50.8,167.64) v4(50.8,132.08) v4(50.8,127) v4(50.8,121.92) v4(50.8,116.84) v4(50.8,111.76) v4(50.8,106.68) v4(50.8,101.6) v4(50.8,96.52) v4(50.8,91.44) v4(50.8,86.36) v4(50.8,81.28) v4(50.8,50.8) v4(50.8,45.72) v4(50.8,40.64) v4(50.8,35.56) v4(50.8,30.48) v4(50.8,25.4) v4(50.8,20.32) v4(50.8,15.24) v4(50.8,10.16) v4(50.8,5.08) v4(50.8,1.65) v4(55.69,52.01) v4(55.69,50.1) v4(55.69,48.2) v4(55.75,168.91) v4(55.75,167) v4(55.75,165.1) v4(55.75,140.97) v4(55.75,139.06) v4(55.75,137.16) v4(55.75,80.01) v4(55.75,78.11) v4(55.75,76.2) v4(55.88,190.63) v4(55.88,187.96) v4(55.88,182.88) v4(55.88,177.8) v4(55.88,172.72) v4(55.88,132.08) v4(55.88,127) v4(55.88,121.92) v4(55.88,116.84) v4(55.88,111.76) v4(55.88,106.68) v4(55.88,101.6) v4(55.88,96.52) v4(55.88,91.44) v4(55.88,86.36) v4(55.88,45.72) v4(55.88,40.64) v4(55.88,35.56) v4(55.88,30.48) v4(55.88,25.4) v4(55.88,20.32) v4(55.88,15.24) v4(55.88,10.16) v4(55.88,5.08) v4(55.88,1.65) v4(58.55,168.91) v4(58.55,167) v4(58.55,165.1) v4(58.55,140.97) v4(58.55,139.06) v4(58.55,137.16) v4(58.55,80.01) v4(58.55,78.11) v4(58.55,76.2) v4(58.48,52.01) v4(58.48,50.1) v4(58.48,48.2) v4(60.96,190.63) v4(60.96,187.96) v4(60.96,182.88) v4(60.96,177.8) v4(60.96,172.72) v4(60.96,167.64) v4(60.96,132.08) v4(60.96,127) v4(60.96,121.92) v4(60.96,116.84) v4(60.96,111.76) v4(60.96,106.68) v4(60.96,101.6) v4(60.96,96.52) v4(60.96,91.44) v4(60.96,86.36) v4(60.96,81.28) v4(60.96,45.72) v4(60.96,40.64) v4(60.96,35.56) v4(60.96,30.48) v4(60.96,25.4) v4(60.96,20.32) v4(60.96,15.24) v4(60.96,10.16) v4(60.96,5.08) v4(60.96,1.65) v4(66.04,190.63) v4(66.04,187.96) v4(66.04,182.88) v4(66.04,177.8) v4(66.04,132.08) v4(66.04,127) v4(66.04,121.92) v4(66.04,116.84) v4(66.04,111.76) v4(66.04,106.68) v4(66.04,101.6) v4(66.04,96.52) v4(66.04,91.44) v4(66.04,86.36) v4(66.04,45.72) v4(66.04,40.64) v4(66.04,35.56) v4(66.04,30.48) v4(66.04,25.4) v4(66.04,20.32) v4(66.04,15.24) v4(66.04,10.16) v4(66.04,5.08) v4(66.04,1.65) v4(71.12,190.63) v4(71.12,187.96) v4(71.12,182.88) v4(71.12,177.8) v4(71.12,132.08) v4(71.12,127) v4(71.12,121.92) v4(71.12,116.84) v4(71.12,111.76) v4(71.12,106.68) v4(71.12,101.6) v4(71.12,96.52) v4(71.12,91.44) v4(71.12,45.72) v4(71.12,40.64) v4(71.12,35.56) v4(71.12,30.48) v4(71.12,25.4) v4(71.12,20.32) v4(71.12,15.24) v4(71.12,10.16) v4(71.12,5.08) v4(71.12,1.65) v4(76.2,190.63) v4(76.2,187.96) v4(76.2,45.72) v4(76.2,40.64) v4(76.2,35.56) v4(76.2,30.48) v4(76.2,25.4) v4(76.2,20.32) v4(76.2,15.24) v4(76.2,10.16) v4(76.2,5.08) v4(76.2,1.65) v4(81.28,190.63) v4(81.28,187.96) v4(81.28,116.84) v4(81.28,106.68) v4(81.28,101.6) v4(81.28,30.48) v4(81.28,25.4) v4(81.28,15.24) v4(81.28,10.16) v4(81.28,5.08) v4(81.28,1.65) v4(86.36,190.63) v4(86.36,187.96) v4(86.36,116.84) v4(86.36,106.68) v4(86.36,101.6) v4(86.36,30.48) v4(86.36,25.4) v4(86.36,20.32) v4(86.36,15.24) v4(86.36,10.16) v4(86.36,5.08) v4(86.36,1.65) v4(89.66,149.73) v4(89.66,148.97) v4(89.66,147.7) v4(89.66,146.94) v4(91.44,190.63) v4(91.44,187.96) v4(91.44,147.32) v4(91.44,144.78) v4(91.44,142.24) v4(91.44,58.42) v4(91.44,55.88) v4(91.44,53.34) v4(91.44,15.24) v4(91.44,10.16) v4(91.44,5.08) v4(91.44,1.65) v4(93.98,160.02) v4(93.98,157.48) v4(93.98,154.94) v4(93.98,152.4) v4(93.98,149.86) v4(93.98,147.32) v4(93.98,144.78) v4(93.98,142.24) v4(93.98,71.12) v4(93.98,68.58) v4(93.98,66.04) v4(93.98,63.5) v4(93.98,60.96) v4(93.98,58.42) v4(93.98,55.88) v4(93.98,53.34) v4(95.76,149.73) v4(95.76,148.97) v4(95.76,147.7) v4(95.76,146.94) v4(96.52,190.63) v4(96.52,187.96) v4(96.52,160.02) v4(96.52,157.48) v4(96.52,156.21) v4(96.52,154.94) v4(96.52,153.67) v4(96.52,152.4) v4(96.52,71.12) v4(96.52,68.58) v4(96.52,67.31) v4(96.52,66.04) v4(96.52,64.77) v4(96.52,63.5) v4(96.52,15.24) v4(96.52,10.16) v4(96.52,5.08) v4(96.52,1.65) v4(98.68,75.06) v4(99.69,163.32) v4(101.6,190.63) v4(101.6,187.96) v4(101.6,111.76) v4(101.6,106.68) v4(101.6,101.6) v4(101.6,20.32) v4(101.6,15.24) v4(101.6,10.16) v4(101.6,5.08) v4(101.6,1.65) v4(106.68,190.63) v4(106.68,101.6) v4(106.68,15.24) v4(106.68,10.16) v4(106.68,5.08) v4(106.68,1.65) v4(111.76,190.63) v4(111.76,45.72) v4(111.76,40.64) v4(111.76,35.56) v4(111.76,15.24) v4(111.76,10.16) v4(111.76,5.08) v4(111.76,1.65) v4(116.84,190.63) v4(116.84,132.08) v4(116.84,127) v4(116.84,121.92) v4(116.84,116.84) v4(116.84,111.76) v4(116.84,106.68) v4(116.84,101.6) v4(116.84,45.72) v4(116.84,40.64) v4(116.84,35.56) v4(116.84,30.48) v4(116.84,25.4) v4(116.84,20.32) v4(116.84,15.24) v4(116.84,10.16) v4(116.84,5.08) v4(116.84,1.65) v4(121.92,190.63) v4(121.92,45.72) v4(121.92,40.64) v4(121.92,35.56) v4(121.92,30.48) v4(121.92,25.4) v4(121.92,20.32) v4(121.92,15.24) v4(121.92,10.16) v4(121.92,5.08) v4(121.92,1.65) v4(126.24,169.93) v4(126.24,168.02) v4(126.24,166.12) v4(126.24,139.95) v4(126.24,138.05) v4(126.24,136.14) v4(126.24,81.03) v4(126.24,79.12) v4(126.24,77.22) v4(126.24,51.05) v4(126.24,49.15) v4(126.24,47.24) v4(127,190.63) v4(127,172.72) v4(127,132.08) v4(127,127) v4(127,121.92) v4(127,116.84) v4(127,111.76) v4(127,106.68) v4(127,101.6) v4(127,96.52) v4(127,91.44) v4(127,40.64) v4(127,35.56) v4(127,30.48) v4(127,25.4) v4(127,20.32) v4(127,15.24) v4(127,10.16) v4(127,5.08) v4(127,1.65) v4(129.03,169.93) v4(129.03,168.02) v4(129.03,166.12) v4(129.03,139.95) v4(129.03,138.05) v4(129.03,136.14) v4(129.03,81.03) v4(129.03,79.12) v4(129.03,77.22) v4(129.03,51.05) v4(129.03,49.15) v4(129.03,47.24) v4(132.08,190.63) v4(132.08,187.96) v4(132.08,182.88) v4(132.08,132.08) v4(132.08,127) v4(132.08,121.92) v4(132.08,116.84) v4(132.08,111.76) v4(132.08,106.68) v4(132.08,101.6) v4(132.08,96.52) v4(132.08,91.44) v4(132.08,45.72) v4(132.08,40.64) v4(132.08,35.56) v4(132.08,30.48) v4(132.08,25.4) v4(132.08,20.32) v4(132.08,15.24) v4(132.08,10.16) v4(132.08,5.08) v4(132.08,1.65) v4(137.16,190.63) v4(137.16,187.96) v4(137.16,182.88) v4(137.16,177.8) v4(137.16,172.72) v4(137.16,132.08) v4(137.16,127) v4(137.16,121.92) v4(137.16,116.84) v4(137.16,111.76) v4(137.16,106.68) v4(137.16,101.6) v4(137.16,96.52) v4(137.16,91.44) v4(137.16,81.28) v4(137.16,50.8) v4(137.16,45.72) v4(137.16,40.64) v4(137.16,35.56) v4(137.16,30.48) v4(137.16,25.4) v4(137.16,20.32) v4(137.16,15.24) v4(137.16,10.16) v4(137.16,5.08) v4(137.16,1.65) v4(140.84,169.93) v4(140.84,168.02) v4(140.84,166.12) v4(140.84,140.08) v4(140.84,138.18) v4(140.84,136.27) v4(140.84,81.03) v4(140.84,79.12) v4(140.84,77.22) v4(140.84,51.18) v4(140.84,49.28) v4(140.84,47.37) v4(142.24,190.63) v4(142.24,187.96) v4(142.24,182.88) v4(142.24,177.8) v4(142.24,172.72) v4(142.24,132.08) v4(142.24,127) v4(142.24,121.92) v4(142.24,116.84) v4(142.24,111.76) v4(142.24,106.68) v4(142.24,101.6) v4(142.24,96.52) v4(142.24,91.44) v4(142.24,45.72) v4(142.24,40.64) v4(142.24,35.56) v4(142.24,30.48) v4(142.24,25.4) v4(142.24,20.32) v4(142.24,15.24) v4(142.24,10.16) v4(142.24,5.08) v4(142.24,1.65) v4(143.64,169.93) v4(143.64,168.02) v4(143.64,166.12) v4(143.64,140.08) v4(143.64,138.18) v4(143.64,136.27) v4(143.64,81.03) v4(143.64,79.12) v4(143.64,77.22) v4(143.64,51.18) v4(143.64,49.28) v4(143.64,47.37) v4(147.32,190.63) v4(147.32,187.96) v4(147.32,182.88) v4(147.32,177.8) v4(147.32,172.72) v4(147.32,167.64) v4(147.32,50.8) v4(147.32,45.72) v4(147.32,40.64) v4(147.32,35.56) v4(147.32,30.48) v4(147.32,25.4) v4(147.32,20.32) v4(147.32,15.24) v4(147.32,10.16) v4(147.32,5.08) v4(147.32,1.65) v4(152.4,190.63) v4(152.4,187.96) v4(152.4,182.88) v4(152.4,177.8) v4(152.4,172.72) v4(152.4,167.64) v4(152.4,50.8) v4(152.4,45.72) v4(152.4,40.64) v4(152.4,35.56) v4(152.4,30.48) v4(152.4,25.4) v4(152.4,20.32) v4(152.4,15.24) v4(152.4,10.16) v4(152.4,5.08) v4(152.4,1.65) v4(157.48,190.63) v4(157.48,187.96) v4(157.48,182.88) v4(157.48,177.8) v4(157.48,172.72) v4(157.48,167.64) v4(157.48,50.8) v4(157.48,45.72) v4(157.48,40.64) v4(157.48,35.56) v4(157.48,30.48) v4(157.48,25.4) v4(157.48,20.32) v4(157.48,15.24) v4(157.48,10.16) v4(157.48,5.08) v4(157.48,1.65) v4(162.56,190.63) v4(162.56,187.96) v4(162.56,182.88) v4(162.56,177.8) v4(162.56,172.72) v4(162.56,167.64) v4(162.56,50.8) v4(162.56,45.72) v4(162.56,40.64) v4(162.56,35.56) v4(162.56,30.48) v4(162.56,25.4) v4(162.56,20.32) v4(162.56,15.24) v4(162.56,10.16) v4(162.56,5.08) v4(162.56,1.65) v4(167.64,190.63) v4(167.64,187.96) v4(167.64,182.88) v4(167.64,177.8) v4(167.64,172.72) v4(167.64,167.64) v4(167.64,101.6) v4(167.64,96.52) v4(167.64,91.44) v4(167.64,86.36) v4(167.64,81.28) v4(167.64,76.2) v4(167.64,71.12) v4(167.64,66.04) v4(167.64,60.96) v4(167.64,55.88) v4(167.64,50.8) v4(167.64,45.72) v4(167.64,40.64) v4(167.64,35.56) v4(167.64,30.48) v4(167.64,25.4) v4(167.64,20.32) v4(167.64,15.24) v4(167.64,10.16) v4(167.64,5.08) v4(167.64,1.65) v4(172.72,190.63) v4(172.72,187.96) v4(172.72,182.88) v4(172.72,177.8) v4(172.72,167.64) v4(172.72,162.56) v4(172.72,157.48) v4(172.72,152.4) v4(172.72,101.6) v4(172.72,96.52) v4(172.72,81.28) v4(172.72,76.2) v4(172.72,60.96) v4(172.72,55.88) v4(172.72,50.8) v4(172.72,45.72) v4(172.72,40.64) v4(172.72,35.56) v4(172.72,30.48) v4(172.72,25.4) v4(172.72,20.32) v4(172.72,15.24) v4(172.72,10.16) v4(172.72,5.08) v4(172.72,1.65) v4(177.8,177.8) v4(177.8,172.72) v4(177.8,101.6) v4(177.8,96.52) v4(177.8,81.28) v4(177.8,76.2) v4(177.8,60.96) v4(177.8,50.8) v4(177.8,30.48) v4(177.8,25.4) v4(177.8,20.32) v4(177.8,15.24) v4(183.77,182.25) v4(183.77,177.16) v4(183.77,172.09) v4(183.77,167) v4(183.77,161.93) v4(183.77,156.84) v4(183.77,151.76) v4(183.77,146.69) v4(183.77,141.6) v4(183.77,136.53) v4(183.77,131.44) v4(183.77,126.36) v4(183.77,121.28) v4(183.77,116.2) v4(183.77,111.12) v4(183.77,106.05) v4(183.77,100.97) v4(183.77,95.89) v4(183.77,90.81) v4(183.77,85.72) v4(183.77,80.64) v4(183.77,75.56) v4(183.77,70.48) v4(183.77,65.41) v4(183.77,60.33) v4(183.77,55.24) v4(183.77,50.16) v4(183.77,45.09) v4(183.77,40.01) v4(183.77,34.92) v4(183.77,29.84) v4(183.77,24.77) v4(183.77,19.68) v4(183.77,14.61) v4(183.77,9.53)
